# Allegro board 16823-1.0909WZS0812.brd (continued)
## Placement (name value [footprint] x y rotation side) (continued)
R6518  0R0402-PAD-2-GP  [0R0402-PAD-1]  143.21 18.16 180 bottom
R6519  0R0402-PAD-2-GP  [0R0402-PAD-1]  144.05 18.16 180 bottom
R6520  0R0402-PAD-2-GP  [0R0402-PAD-1]  132.34 26.52 180 bottom
R6521  0R2J-2-GP  [R402H16]  137.42 27.56 270 bottom
R6522  100R3J-4-GP  [R603H22]  133.26 22.58 270 bottom
R6523  0R2J-2-GP  [R402H16]  136.17 22.99 180 bottom
R6524  2K2R2J-2-GP  [R402H16]  133.69 17.74 270 bottom
R6525  10KR2J-3-GP  [R402H16]  139.12 27.82 270 bottom
R6601  0R2J-2-GP  [R402H16]  171.61 24.54 0 top
R6602  0R2J-2-GP  [R402H16]  171.89 21.54 0 top
R6603  0R3J-0-U-GP  [R603H22]  172.04 14.81 0 top
R7001  10KR2J-3-GP  [R402H16]  176.38 50.74 0 top
R7002  0R2J-2-GP  [R402H16]  174.13 43.88 180 top
R7003  0R2J-2-GP  [R402H16]  176.18 42.9 270 top
R7004  10KR2J-3-GP  [R402H16]  175.51 50.74 0 top
R7005  0R2J-2-GP  [R402H16]  174.62 50.74 0 top
R7006  100KR2J-1-GP  [R402H16]  166.78 83.52 270 top
R7007  100KR2J-1-GP  [R402H16]  160.08 83.56 0 top
R7008  100KR2J-1-GP  [R402H16]  177.04 48.3 0 top
R7009  100KR2J-1-GP  [R402H16]  160.64 81.64 90 top
R7010  0R2J-2-GP  [R402H16]  161.04 83.01 0 top
R7011  1MR2J-1-GP  [R402H16]  159.15 83.56 180 top
R9901  4K7R2F-GP  [R402H16]  39.71 69.14 180 top
R9902  0R2J-2-GP  [R402H16]  64.12 73.1 180 top
R9904  4K7R2F-GP  [R402H16]  47.07 62.18 180 top
R9905  10KR2J-3-GP  [R402H16]  55.43 74.63 0 top
R9906  1KR2J-1-GP  [R402H16]  53.7 74.63 180 top
R9908  0R2J-2-GP  [R402H16]  67.47 75.16 180 top
R9909  1KR2J-1-GP  [R402H16]  46.18 62.18 0 top
R9910  0R2J-2-GP  [R402H16]  64.47 68 90 top
R9912  1KR2J-1-GP  [R402H16]  39.71 67.41 0 top
R9913  0R2J-2-GP  [R402H16]  64.55 70.92 270 top
R9914  0R2J-2-GP  [R402H16]  157.18 83.34 0 bottom
R9915  0R2J-2-GP  [R402H16]  156.32 83.34 0 bottom
R9916  0R2J-2-GP  [R402H16]  65.56 75.03 180 top
R9917  1KR2J-1-GP  [R402H16]  56.27 74.63 180 top
R9918  0R2J-2-GP  [R402H16]  58.05 75.14 0 top
R9919  0R2J-2-GP  [R402H16]  49.54 73.56 90 top
R9920  0R2J-2-GP  [R402H16]  64.55 70.06 90 top
R9921  10KR2J-3-GP  [R402H16]  64.96 72.57 180 top
R9922  0R2J-2-GP  [R402H16]  59.77 75.14 0 top
R9923  0R2J-2-GP  [R402H16]  152.89 83.34 0 bottom
R9924  0R2J-2-GP  [R402H16]  49.54 74.4 90 top
R9925  0R2J-2-GP  [R402H16]  40.09 64.62 90 top
R9926  1KR2J-1-GP  [R402H16]  45.32 62.18 0 top
R9928  0R2J-2-GP  [R402H16]  153.75 83.34 0 bottom
R9929  0R2J-2-GP  [R402H16]  40.09 63.78 90 top
R9930  1KR2J-1-GP  [R402H16]  54.59 74.63 180 top
R9931  0R2J-2-GP  [R402H16]  154.62 83.34 0 bottom
R9932  0R2J-2-GP  [R402H16]  155.46 83.36 0 bottom
RN801  SRN2K2J-1-GP  [ARES2H16]  111.36 98.63 200 bottom
RN802  SRN2K2J-1-GP  [ARES2H16]  25.23 62.26 0 top
RN1201  SRN1KJ-7-GP  [SMD-ARES4H18]  89.77 30.23 90 top
RN1603  SRN10KJ-5-GP  [ARES2H18]  107.73 77.27 290 bottom
RN1606  SRN10KJ-5-GP  [ARES2H18]  107.04 79.17 290 bottom
RN1607  SRN10KJ-5-GP  [ARES2H18]  101.33 91.85 270 bottom
RN1608  SRN10KJ-5-GP  [ARES2H18]  103.11 89.82 270 bottom
RN1701  SRN10KJ-5-GP  [ARES2H18]  108.54 97.56 20 bottom
RN1703  SRN1KJ-7-GP  [SMD-ARES4H18]  90.71 82.6 180 bottom
RN1704  SRN2K2J-1-GP  [ARES2H16]  91.96 85.14 90 bottom
RN1802  SRN100J-3-GP  [SMD-ARES4H18]  128.3 104.83 20 bottom
RN1803  SRN10KJ-5-GP  [ARES2H18]  104.5 75.34 270 bottom
RN1804  SRN20KJ-1-GP  [SMD-ARES4H20]  103.51 97.61 40 bottom
RN1904  SRN10KJ-5-GP  [ARES2H18]  108.69 75.47 290 bottom
RN1905  0R8P4R-PAD-1-GP  [0R8P4R-PAD-1]  103.97 84.33 90 top
RN1906  SRN2K2J-1-GP  [ARES2H16]  142.73 20.04 270 bottom
RN1907  SRN10KJ-5-GP  [ARES2H18]  86.32 72.54 270 bottom
RN1908  SRN1KJ-7-GP  [SMD-ARES4H18]  69.4 65.84 0 top
RN1909  SRN1KJ-7-GP  [SMD-ARES4H18]  95.84 65.86 270 top
RN1910  SRN10KJ-5-GP  [ARES2H18]  101 140.72 90 bottom
RN1911  SRN10KJ-5-GP  [ARES2H18]  101 143.82 270 bottom
RN1912  SRN10KJ-5-GP  [ARES2H18]  104.12 146.92 270 bottom
RN2101  SRN10KJ-5-GP  [ARES2H18]  125.66 110.26 90 bottom
RN2401  SRN2K2J-1-GP  [ARES2H16]  171.28 52.63 180 top
RN2402  SRN10KJ-5-GP  [ARES2H18]  166.4 54.61 90 top
RN2404  SRN10KJ-5-GP  [ARES2H18]  170.52 65.18 90 top
RN2406  SRN10KJ-5-GP  [ARES2H18]  167.34 75.74 270 bottom
RN2601  SRN2K2J-1-GP  [ARES2H16]  74.18 67.01 90 bottom
RN2901  SRN2K2J-1-GP  [ARES2H16]  168.61 21.06 0 bottom
RN4302  SRN100J-4-GP  [ARES8-CN24H20]  150.2 178.16 270 top
RN5501  SRN100J-4-GP  [ARES8-CN24H20]  104.22 176.48 0 top
RN5502  SRN100J-3-GP  [SMD-ARES4H18]  113.8 168.28 180 top
RN5701  SRN2K2J-1-GP  [ARES2H16]  19.21 54.69 270 top
RN5702  SRN470J-3-GP  [ARES8-CN24H20]  15.93 46.59 90 bottom
RN5703  SRN470J-3-GP  [ARES8-CN24H20]  15.96 50.28 90 bottom
RN6401  SRN100J-3-GP  [SMD-ARES4H18]  167.55 114.81 90 bottom
RN6503  SRN33J-5-GP-U  [SMD-ARES4H18]  140.11 19.71 0 bottom
RN6504  SRN10KJ-5-GP  [ARES2H18]  138.06 21.47 180 bottom
RTC1  BAT-40-42010-00211RHF-GP-U2  [40-42010-00211RHF-U2]  35.35 23.5 180 bottom
SPI251  W25Q128FWSIQ-GP  [SOIC8-1H86]  60.37 48.99 270 bottom
SPI252  MX25U1001EMI-14G-GP  [SOIC8H69]  167.04 30.69 90 bottom
SPK1  ACES-CON4-29-GP  [50224-0040N-001]  155.2 8.3 180 bottom
SPR1  SPRING-63-GP  [SPR5630H142]  71.4 74.7 90 top
SPR2  SPRING-43-GP-U  [SPR4527H308]  158.56 34.3 270 bottom
SPR3  SPRING-63-GP  [SPR5630H142]  33.4 68.3 0 bottom
SPR4  SPRING-63-GP  [SPR5630H142]  71.4 47.3 90 top
SPR5  SPRING-63-GP  [SPR5630H142]  59.4 72.3 0 bottom
TP1  STAR-CON8-2-GP  [106H08-011001-A2-R]  138.9 10.1 90 bottom
TP509  TPAD14-OP-GP  [TPAD14-OP]  124.75 82.86 0 top
TP510  TPAD14-OP-GP  [TPAD14-OP]  126.58 81.41 0 top
TP1201  TPAD14-OP-GP  [TPAD14-OP]  143.8 28.63 270 top
TP1802  TPAD14-OP-GP  [TPAD14-OP]  117.76 91.37 0 top
TP1803  TPAD14-OP-GP  [TPAD14-OP]  126.98 103.23 180 bottom
TP1804  TPAD14-OP-GP  [TPAD14-OP]  113.49 98.27 180 bottom
TP1901  TPAD14-OP-GP  [TPAD14-OP]  112.78 87.89 0 top
TP2101  TPAD14-OP-GP  [TPAD14-OP]  122.56 101.6 180 bottom
TP2102  TPAD14-OP-GP  [TPAD14-OP]  121.17 101.12 180 bottom
TP2104  TPAD14-OP-GP  [TPAD14-OP]  118.6 92.51 0 top
TP2105  TPAD14-OP-GP  [TPAD14-OP]  115.6 99.04 180 bottom
TP2407  TPAD14-OP-GP  [TPAD14-OP]  165.82 69.88 180 bottom
TP2408  TPAD14-OP-GP  [TPAD14-OP]  156.04 55.25 180 bottom
TP2410  TPAD14-OP-GP  [TPAD14-OP]  175.19 69.9 180 bottom
TP2412  TPAD14-OP-GP  [TPAD14-OP]  156.67 65.08 180 bottom
TP2701  TPAD14-OP-GP  [TPAD14-OP]  156.9 24.82 180 bottom
TP4301  TPAD14-OP-GP  [TPAD14-OP]  148.42 175.11 0 top
TP4501  TPAD14-OP-GP  [TPAD14-OP]  52.71 44.1 0 top
TP6001  TPAD14-OP-GP  [TPAD14-OP]  171.97 149.61 0 top
TP6002  TPAD14-OP-GP  [TPAD14-OP]  171.76 148.59 180 bottom
TP6101  TPAD14-OP-GP  [TPAD14-OP]  143.09 157.05 0 top
TP6102  TPAD14-OP-GP  [TPAD14-OP]  144.58 155.68 0 top
TP6103  TPAD14-OP-GP  [TPAD14-OP]  156.4 163.43 180 bottom
TP6301  TPAD14-OP-GP  [TPAD14-OP]  59.42 62.92 0 top
TP6302  TPAD14-OP-GP  [TPAD14-OP]  58.17 62.94 0 top
TP6303  TPAD14-OP-GP  [TPAD14-OP]  56.93 62.97 0 top
TP6304  TPAD14-OP-GP  [TPAD14-OP]  53.42 62.97 0 top
TR5501  FILTER-4P-137-GP-U  [L125100-4P-4H28]  117.18 164.37 270 top
U1801  U74LVC1G08G-AL5-R-GP-U  [SC70-5-1H44]  95.63 92.21 270 bottom
U2404  G2129TL1U-GP  [SC70-6H44]  151.62 65.41 270 bottom
U2601  NCT7718W-GP  [MSOP8-1H44]  78.54 71.99 270 bottom
U3601  G524B2T11U-GP  [SOT-23-5H58]  22.33 37.09 270 top
U3602  G524B2T11U-GP  [SOT-23-5H58]  162.8 9.53 270 bottom
U4001  APL3523AQBI-TRG-GP  [SON14J3020-G2610H32]  27.74 51.23 90 top
U4002  APE8937GN2-GP-U  [DFN8G2-G1710-U1H32]  130.59 115.04 90 bottom
U4003  U74LVC1G08G-AL5-R-GP-U  [SC70-5-1H44]  22.28 60.86 180 bottom
U4004  U74LVC1G08G-AL5-R-GP-U  [SC70-5-1H44]  25.48 60.86 180 bottom
U5501  RT9724GB-GP  [SOT-23-5H51]  102.42 158.5 90 top
U6001  SN75LVCP601RTJR-GP  [QFN20-G2D25H32]  164.98 41.28 270 bottom
U6301  KLMBG4GEND-B031-GP  [BGA153G115130-1H40]  55.81 61.9 90 bottom
U7001  LNG2DMTR-GP  [LGA12G2H40]  174.81 47.68 0 top
USB1  SKT-USB13-179-GP  [SKT-USB13-157164-1]  4.87 31.55 90 bottom
USB2  SKT-USB13-179-GP  [SKT-USB13-157164-1]  4.87 13.05 90 bottom
WLAN1  SKT-NGFF75P-96-GP  [SM3ZS067U410TAR1000R-DT]  148.9 159 90 bottom
X1801  XTAL-32D768KHZ-68-GP  [SMD49-6914-0603H56]  92.31 78.54 225 bottom
X1901  XTAL-19D2MHZ-21-GP  [OSC-3225-4P-4H32]  130.82 108 200 bottom
XDP1  PAD-60P-1-NSP-GP  [PAD-60P-1-NSP]  52.18 68.33 180 top

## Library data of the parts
AFTP2501 AFTP2502 AFTP2901-AFTP2904 AFTP2908 AFTP2909 AFTP3501-AFTP3508 AFTP4301-AFTP4315 AFTP5501-AFTP5523 AFTP6101 AFTP6103 AFTP6104 AFTP6106-AFTP6108 AFTP6401-AFTP6404 AFTP6501-AFTP6503 AFTP6505-AFTP6508 AFTP6510-AFTP6513 AFTP6515-AFTP6540 AFTP6565-AFTP6567 AFTP6601-AFTP6612 = AFTE14P-75: tolerance: ZZ.AFT14.101
BATT1 = C144KA-108A7-L-1: tolerance: 20.81775.008
BATT2 = 50312-00841-001: tolerance: 020.80533.0008
C601 C1001-C1030 C1101-C1104 C1106-C1113 C1206-C1210 C1213-C1215 C1801 C1802 C2443 C2444 C2703 C2704 C3518 C3604 C3606 C4031 C5509 C5536 C6009 C6010 C6012 C6301 PC1101 PC4407 PC5028 PC5103 PC5109 PC5124 = C402H22: tolerance: 78.10523.5FL
C1201-C1203 C1205 C1211 C1212 C1216-C1218 C1220 C2602 C2707 C2709 C2712 C2713 C2723 C2729 C2901 C2903 C2904 C2906 C2908 C4002 C4004-C4006 C6102 C7001 C9901 PC1003 PC1004 PC1047 PC1052 PC5003 PC5004 PC5007 PC5008 PC5010 PC5024 PC5025 = C603H38: tolerance: 78.10610.5BL
C1223 C1224 C1805 C2417 C2418 C2428-C2432 C2436 C2438-C2442 C2445-C2447 C2502 C2504 C2601 C2605 C2606 C2706 C2708 C2710 C2714 C2717 C2719-C2721 C2728 C3509 C3517 C3605 C4010 C4011 C4030 C5502 C5538 C6020 C6022 C6101 C6103 C6303 C6305 C6401 C6501-C6504 C6601 C7002 C7003 C9902-C9905 EC4001-EC4005 EC6401 PC4501 PC4517 PC4518 = C402H22: tolerance: 78.10421.2FL
C1601 = C402H22: tolerance: 78.10421.2FL; signal model: Graser_C1601
C1602 = C402H22: tolerance: 78.10421.2FL; signal model: Graser_C1602
C1803 C1804 = C402H22: tolerance: 78.4R074.1FL
C1901 C1902 = C402H22: tolerance: 78.3R974.1FL
C2401 C2722 EC2708 EC5504 EC5505 = C402H22: tolerance: 78.22034.1FL
C2414 C2416 C2433 C2705 C5514 PC5023 PC5034 = C603H36: tolerance: 78.22523.5BL
C2501 C2503 = C402H22: tolerance: 078.10610.C5F1
C2603 C4003 = C402H22: tolerance: 78.47124.2FL
C2604 PC5011-PC5013 PC5026 PC5027 = C402H22: tolerance: 78.22224.2FL
C2607 EC2905-EC2908 PC4422 = C402H22: tolerance: 78.10134.1FL
C2701 C2702 C2711 C2715 C2716 C2718 C5510 C5515 C5516 C6302 C6304 PC4524 PC4526 = C603H36: tolerance: 78.47520.5BL
C2905 C2907 C2909 C2910 C4014 C4033 C5503 EC2702-EC2706 EC2901-EC2904 EC6403 PC5105 PC5122 PC5125 = C402H22: tolerance: 78.10224.2FL
C3501 = C402H22: tolerance: 78.10421.2FL; signal model: Graser_C3501
C3502 = C402H22: tolerance: 78.10421.2FL; signal model: Graser_C3502
C3507 = C402H22: tolerance: 78.10421.2FL; signal model: Graser_C3507
C3508 = C402H22: tolerance: 78.10421.2FL; signal model: Graser_C3508
C3515 C3601 C3602 PC5005 PC5006 PC5009 PC5017-PC5020 PC5022 PC5030-PC5032 = C805H58: tolerance: 78.22610.51L
C3607 = C1206H71: tolerance: 78.10710.52L
C5501 PC4408 PC4509 PC4529 = C805H54: tolerance: 78.47522.51L
C5504 = C402H22: tolerance: 78.10421.2FL; signal model: Graser_C5504
C5505 = C402H22: tolerance: 78.10421.2FL; signal model: Graser_C5505
C5506 = C402H22: tolerance: 78.10421.2FL; signal model: Graser_C5506
C5507 = C402H22: tolerance: 78.10421.2FL; signal model: Graser_C5507
C5511 EC4302 EC4307 EC4401 EC4402 EC5501-EC5503 EC5701 EC6402 EC6404 EC8901-EC8931 PC1023 PC1038 PC4402 PC4420 PC4421 PC4423 PC5015 PC5021 PC5029 PC5112 = C402H22: tolerance: 78.10422.5FL
C5512 = C402H22: tolerance: 78.10421.2FL; signal model: Graser_C5512
C5513 = C402H22: tolerance: 78.10421.2FL; signal model: Graser_C5513
C5701 = C402H22: tolerance: 78.10421.2FL; signal model: Graser_C5701
C5702 = C402H22: tolerance: 78.10421.2FL; signal model: Graser_C5702
C5703 = C402H22: tolerance: 78.10421.2FL; signal model: Graser_C5703
C5704 = C402H22: tolerance: 78.10421.2FL; signal model: Graser_C5704
C5705 = C402H22: tolerance: 78.10421.2FL; signal model: Graser_C5705
C5706 = C402H22: tolerance: 78.10421.2FL; signal model: Graser_C5706
C5707 = C402H22: tolerance: 78.10421.2FL; signal model: Graser_C5707
C5708 = C402H22: tolerance: 78.10421.2FL; signal model: Graser_C5708
C6001-C6008 PC4303-PC4305 PC4412 PC4425 PC4531 = C402H22: tolerance: 78.10324.2FL
C6011 = C402H22: tolerance: 78.10324.2FL; signal model: Graser_C6011
C6013 = C402H22: tolerance: 78.10324.2FL; signal model: Graser_C6013
C6014 = C402H22: tolerance: 78.10324.2FL; signal model: Graser_C6014
C6015 = C402H22: tolerance: 78.10324.2FL; signal model: Graser_C6015
C6016 = C402H22: tolerance: 78.10324.2FL; signal model: Graser_C6016
C6017 = C402H22: tolerance: 78.10324.2FL; signal model: Graser_C6017
C6018 = C402H22: tolerance: 78.10324.2FL; signal model: Graser_C6018
C6019 = C402H22: tolerance: 78.10324.2FL; signal model: Graser_C6019
C6021 C6023 C6024 = C805H54: tolerance: 78.10623.51L
CPU1 = BGA1296M3124H56: tolerance: ZZ.00CPU.061
D1601 = SOT23-2D4-312H44: tolerance: 83.00016.P11
D2401 = SOD323AKH38: tolerance: 83.R2004.G8F
D2701 D4001 D5501 D5502 = SOT23-2D4-312H48: tolerance: 75.00054.E7D
D4304-D4306 PD4302 = SOT23-2D4-312H44: tolerance: 75.00099.O7D
D5701 = SOT23-2D4-312H44: tolerance: 83.00056.Y11
DB1 = PAD-87212-1002N: tolerance: ZZ.00PAD.GV1
DB3 = 88459-047N: tolerance: 20.F1897.004
DCIN1 DCIN2 = 50458-00601-W01: tolerance: 20.F2132.006
DM1 = AS0A621-J4R6-7H-U: tolerance: 62.10024.S21
EC1801 EC1901 EC1902 EC2001 EC2002 EC2102 EC2503 EC2505 EC2709 EC4306 EC4309 EC4310 PC5033 = C402H22: tolerance: 78.10034.1FL
EC2401-EC2403 ED1201 ED1202 ED1803-ED1809 ED6401 = SOD882-10D6-1H20: tolerance: 83.05725.0A0
EC2501 EC2502 EC2504 EC2506 = C402H22: tolerance: 78.4R7B4.1FL
EC4301 PC4306 PC4416 PC4417 PC4426 PC4519 PC4527 PC4528 PC5102 PC5104 PC5113 PC5114 PC5119 PC5128 PC5131 = C805H56: tolerance: 78.10622.51L
EC4308 PC4302 PC4401 PC4403 PC4404 PC4409 PC4419 PC4516 PC4525 PC4530 PC4535 PC5106 PC5115 PC5116 PC5121 = C603H36: tolerance: 78.10424.2BL
EC5506 = C402H22: tolerance: 78.6R074.1FL
EC5507 EC6501-EC6506 = C402H22: tolerance: 78.33034.1FL
ED5701-ED5703 EU3501 EU3504 = SLP2510P8-1H22: tolerance: 075.00550.0071
ED6601 EU3502 EU5501 = SOT-6H58: tolerance: 075.09904.0A7C
EL3503 = L125100-4P-4H28: tolerance: 68.01012.20B; signal model: Graser_EL3503
EL3504 = L125100-4P-4H28: tolerance: 68.01012.20B; signal model: Graser_EL3504
EL4301-EL4304 R603 R701 R2708 R6004 R6025 = 0R0805-PAD-1-U: tolerance: ZZ.00PAD.M31
EL6601 = L125100-4P-4H28: tolerance: 68.01012.20B; signal model: Graser_EL6601
EL6602 = L125100-4P-4H28: tolerance: 68.01012.20B; signal model: Graser_EL6602
ER3505 = 0R0402-PAD-1: tolerance: ZZ.00PAD.M11; signal model: Graser_ER3505
ER3506 = 0R0402-PAD-1: tolerance: ZZ.00PAD.M11; signal model: Graser_ER3506
ER3509 = 0R0402-PAD-1: tolerance: ZZ.00PAD.M11; signal model: Graser_ER3509
ER3510 = 0R0402-PAD-1: tolerance: ZZ.00PAD.M11; signal model: Graser_ER3510
ER3511 = 0R0402-PAD-1: tolerance: ZZ.00PAD.M11; signal model: Graser_ER3511
ER3512 = 0R0402-PAD-1: tolerance: ZZ.00PAD.M11; signal model: Graser_ER3512
ER6102 = 0R0402-PAD-1: tolerance: ZZ.00PAD.M11; signal model: Graser_ER6102
ER6103 = 0R0402-PAD-1: tolerance: ZZ.00PAD.M11; signal model: Graser_ER6103
EU6001 = DFN10G2510H26: tolerance: 75.01045.073
F5501 F5503 = POLYSW-4633-UH43: tolerance: 69.50007.A31
F5502 = POLYSW-2114H50: tolerance: 69.50007.921
F5701 = POLYSW-2114H30: tolerance: 69.48001.081
FC3503-FC3506 = C402H22: tolerance: 78.1R074.1FL
G1801 G6401 G6402 = CON2O-U: tolerance: ZZ.CON2O.XXX
H1-H4 = HOLE335R115: tolerance: ZZ.00PAD.D01
H5 = HOLE276R91: tolerance: ZZ.00PAD.CZ1
H6-H9 = HOLE335R178: tolerance: ZZ.00PAD.7F1
H10 = HOLE384X421R115: tolerance: ZZ.SCREW.681
HDA27 = QFN48J6-G465H40: tolerance: 071.03246.0003
HDD1 = 132F12-010000-A2-R: tolerance: 020.K0125.0012
HDMI1 = SKT-HDMI23-188137-5: tolerance: 022.10025.0161
HS1 = STF236R128H101: tolerance: 34.4YG18.201
IOBD1 = 51519-03001-W02-U2: tolerance: 20.K0510.030
KB1 = 196370-30041-3: tolerance: 20.K0621.030
KB2 = 50699-03001-W01: tolerance: 020.K0254.0030
KBBL1 = 51678-00401-W01: tolerance: 020.K0206.0004
KBC24 = LQFP128H63: tolerance: 071.00985.000G
L2701 = L603H38: tolerance: 68.00115.091
LCD1 = 20455-040E-12: tolerance: 20.F1407.040
LED1 = LED3020-3P-19H44: tolerance: 083.1212A.0070
ODD1 ODD2 = 51519-02001-W03-U1: tolerance: 20.K0708.020
PC1001 PC1002 PC1006-PC1022 PC1024-PC1028 PC1030-PC1037 PC1039-PC1046 PC1048-PC1051 PC1102 PC1103 PC5035 PC5036 PC5101 PC5107 PC5108 PC5110 PC5117 PC5118 PC5120 PC5123 PC5126 PC5127 PC5129 PC5130 = C603H40: tolerance: 78.22610.5BL
PC4301 = C805H58: tolerance: 78.10594.41L
PC4406 PC4415 PC4418 = C805H56: tolerance: 78.10622.LAL
PC4410 = C603H36: tolerance: 78.47422.5BL
PC4411 = C402H22: tolerance: 78.47322.2FL
PC4413 = C603H36: tolerance: 78.33224.2BL
PC4433 = C402H22: tolerance: 78.47420.5FL
PC4434 = C603H36: tolerance: 78.10522.5BL
PC4435 = C402H22: tolerance: 78.22224.2FLDL
PC4520 = C603: tolerance: 78.33124.2BL
PC4522 PC4523 = C402H22: tolerance: 78.18034.1FL
PC4536 = C603: tolerance: 78.56124.2BL
PC5014 = C402H22: tolerance: 78.68124.2FL
PC5016 = C402H24: tolerance: 78.12224.2FL
PD4301 PD4401 = SOD323AKH38: tolerance: 83.2R004.08F
PD4303 = SOT-23-10H44: tolerance: 83.0024V.0A1
PD4304 = SOD123AK-2H43: tolerance: 83.SMF18.AAH
PD4404 = SOD323AKH42: tolerance: 83.04148.D1H
PG4402 PG4403 PG4407-PG4411 PG4517-PG4529 PG4531-PG4538 PG4540-PG4545 PG5003-PG5005 PG5007-PG5009 PG5011 PG5012 PG5014 PG5016 PG5101-PG5129 = GAP-CLOSE-PWR-3: tolerance: ZZ.CLOSE.001
PL4401 = L686647-127318H119: tolerance: 68.5R610.10U
PL4501 PL4502 = L7066-1830-UH119: tolerance: 68.2R210.20B
PL5001 = L2520-D620H48: tolerance: 068.2R210.1231
PL5002 = L32250525H48: tolerance: 068.1R010.1701
PL5003 = L2520-D620H48: tolerance: 068.1R010.1281
PL5101 = L7066-1630-1H119: tolerance: 68.R5610.10W
PL5102 = L7066-1830-UH119: tolerance: 68.R4710.10M
PL5103 = L7066-1830-UH119: tolerance: 68.R2210.10V
PQ4301 Q6401 = SOT23DGS2D4H48: tolerance: 84.05067.031
PQ4302 Q2601 Q2604 Q2902-Q2906 Q2908 Q5501 Q5504 = SOT23CBE2D4H44: tolerance: 84.T3904.H11
PQ4304 = SOT323CBE2D2H40: tolerance: 84.05212.B11
PQ4305 = SC70-2D2-312H44: tolerance: 84.00024.01K
PQ4306 Q7001 = SOT-363H44: tolerance: 84.2N702.A3F
PQ4402 PQ4407 PQ4408 PQ4410 Q1701 Q1902 Q1905 Q2403 Q2603 Q4001-Q4003 = SOT-363H44: tolerance: 75.27002.F7C
PQ4409 Q2401 = SOT23CBE2D4H44: tolerance: 84.T3906.E11
PQ4414 Q1601 Q1801 Q1802 Q2103 Q2104 Q2402 Q2502 Q2602 Q5702 Q5703 Q6505 Q6509 = SOT23DGS2D4H44: tolerance: 84.2N702.J31
PR4302 = R402H16: tolerance: 64.15025.6DL
PR4303 PR4401 PR4506 PR5029 PR5030 R1525 R1605 R1606 R1808 R1811 R1813 R1816 R1824 R1834 R1921 R2018-R2020 R2024 R2025 R2028 R2029 R2106 R2114 R2120 R2122 R2124 R2126 R2400 R2405 R2421 R2426 R2427 R2436 R2441 R2462 R2471-R2473 R2917 R2918 R5536 R5703 R6005 R6007 R6008 R6013 R6014 R6017 R6021 R6024 R6408 R6514 R6525 R7001 R7004 R9905 R9921 = R402H16: tolerance: 63.10334.1DL
PR4304 PR5016 PR5025 R2123 R2717 R5529-R5532 R6524 = R402H16: tolerance: 63.22234.1DL
PR4305 PR4306 R1905 R1908 = R402H16: tolerance: 63.33034.1DL
PR4307 = R603H22: tolerance: 63.24434.15L
PR4308 = R603H22: tolerance: 63.47333.15L
PR4309 PR4312 PR4403 PR4417 PR4419 PR4425 PR4430 PR4434 PR4438 PR4439 PR4469 PR4474 PR4534 PR5014 PR5018 R804 R805 R808 R1703 R1807 R1814 R1817 R1826 R2012 R2023 R2115 R2439 R2440 R2442 R2711 R2713 R2726 R2733 R3601 R4002 R4009 R4011 R5501-R5503 R5514 R5515 R5520 R5526-R5528 R5702 R6505 R6507 R6509 R7006-R7009 = R402H16: tolerance: 63.10434.1DL
PR4313 PR4422 PR4426 PR4502 PR4505 PR5001 PR5005 PR5010 PR5013 PR5017 PR5023 PR5033 PR5035 PR5037-PR5043 PR5113 R601 R611 R1201 R1213 R1607 R1702 R1804 R1809 R1829 R1830 R1909 R1919 R1924 R2013 R2128 R2129 R2414 R2415 R2422 R2425 R2444 R2497-R2501 R2503 R2505-R2509 R2512 R2529 R2530 R2603 R2611 R2705 R2710 R2718 R2719 R2722 R2724 R2729 R4004 R4301 R5504 R5505 R5517 R5518 R5701 R6001 R6002 R6404 R6405 R6508 R6518-R6520 = 0R0402-PAD-1: tolerance: ZZ.00PAD.M11
PR4314 = R1206H28: tolerance: 63.33232.11L
PR4317 PR4409 PR5105 PR5106 PR5109 R602 R604-R610 R702 R2435 R2720 R2725 R2727 R2728 R2901-R2904 R2906 R2907 R2909 R2911 R2914 R4050 R5512 R5718 R6105 = 0R0603-PAD-1-U: tolerance: ZZ.00PAD.M21
PR4402 PR4416 = R3720H40: tolerance: 64.R0105.7FL
PR4404 = R805H24: tolerance: 63.30231.16L
PR4405 = R402H16: tolerance: 63.47434.1DL
PR4406 PR4418 PR4465 PR4466 PR4468 PR4475 PR4476 PR4501 PR4503 PR4504 PR4525 PR4530 PR4535 PR5045 PR5046 R1801-R1803 R1805 R1818 R1911 R1912 R2014 R2016 R2017 R2117 R2118 R2404 R2411 R2412 R2494 R2511 R2515 R2518 R2601 R2602 R2607 R2609 R2706 R2707 R4005 R4008 R4010 R5510 R5535 R5537 R6003 R6106-R6108 R6310-R6312 R6314 R6315 R6317-R6321 R6323 R6325 R6511 R6515 R6521 R6523 R6601 R6602 R7002 R7003 R7005 R7010 R9902 R9908 R9910 R9913-R9916 R9918-R9920 R9922-R9925 R9928 R9929 R9931 R9932 = R402H16: tolerance: 63.R0034.1DL
PR4407 PR4429 = R402H16: tolerance: 64.30935.6DL
PR4408 = R805H24: tolerance: 63.20031.16L
PR4411 = R402H16: tolerance: 64.10235.6DL
PR4412 PR4415 = R402H16: tolerance: 64.33015.6DL
PR4413 = R402H16: tolerance: 64.16935.L0L
PR4414 = R402H16: tolerance: 63.33534.1DL
PR4420 = R402H16: tolerance: 64.7R505.6DL
PR4421 R2908 R2910 = R402H14: tolerance: 64.10R05.6DL
PR4423 = R402H16: tolerance: 64.59025.6DL
PR4424 = R402H16: tolerance: 64.84515.6DL
PR4427 = R402H16: tolerance: 64.78725.6DL
PR4431 = R402H16: tolerance: 64.47025.6DL
PR4432 PR4433 PR4436 = R402H16: tolerance: 64.12035.6DL
PR4435 PR4473 PR4523 PR5020 R1502 R1508 R1512 R1514 R1519 R1522 R1523 R2430 R2924-R2926 R2928 = R402H16: tolerance: 64.10025.6DL
PR4437 = R402H16: tolerance: 64.16035.6DL
PR4440 PR4529 PR4533 PR5102 PR5112 PR5114 = R805H24: tolerance: 64.2R205.16L
PR4464 = R402H16: tolerance: 63.68434.1DL
PR4470 R803 R7011 = R402H16: tolerance: 63.10534.1DL
PR4471 PR4472 PR4517 R2438 R2443 = R402H16: tolerance: 64.10035.6DL
PR4512 = R402H16: tolerance: 64.66515.6DL
PR4524 PR4528 = R603H22: tolerance: 63.1R534.15L
PR4526 = R402H16: tolerance: 64.97615.6DL
PR4527 = R402H16: tolerance: 64.15425.6DL
PR4531 = R402H16: tolerance: 64.13035.6DL
PR5004 PR5012 PR5034 = R402H14: tolerance: 64.10005.6DL
PR5007 PR5008 = R402H16: tolerance: 63.2R234.1DL
PR5019 = R402H16: tolerance: 64.54905.6DL
PR5021 = R402H16: tolerance: 64.38325.6DL
PR5024 = R402H16: tolerance: 64.21025.6DL
PR5031 PR5101 PR5103 PR5104 = R603H22: tolerance: 63.2R233.15L
PR5032 = R402H16: tolerance: 64.91015.6DL
PR5036 = R402H16: tolerance: 64.15825.6DL
PR5044 R1701 R1815 R1819 R1832 R1835 R1836 R1922 R1923 R2419 R2468 R2493 R2527 R2730 R2919 R2920 R2927 R2929 R4003 R4006 R4007 R4013 R6506 R6516 R9906 R9909 R9912 R9917 R9926 R9930 = R402H16: tolerance: 63.10234.1DL
PR5107 = NTC-402H24-U: tolerance: 069.60013.0001
PR5108 = R402H16: tolerance: 64.56205.6DL
PR5110 = R402H16: tolerance: 64.29415.6DL
PR5111 = R402H16: tolerance: 64.22605.6DL
PT4501 PT4502 = SE361414H178: tolerance: 79.22710.3KL
PT5101 = CT7343H83: tolerance: 79.22719.2BL
PT5102 = CT3528H79: tolerance: 77.C2271.45L
PT5103 = CT7343H83: tolerance: 79.33612.20L
PU4301 PU4402 PU4403 = PPAK-8P-3232H36: tolerance: 84.07403.037
PU4404 = QFN20G3D5-G2D15H40: tolerance: 74.24727.A73
PU4405 PU4406 PU4501 PU4504 PU4505 PU5101-PU5103 = PPAK-8P-3232H36: tolerance: 84.07410.A37
PU4502 PU5104 = PPAK-8P-3232H36: tolerance: 84.07506.037
PU4503 = QFN20-G1D75H32: tolerance: 74.51225.073
PU5001 = QFN52J6-G4D75H32: tolerance: 074.05073.0D73
PU5105 = PPAK-8P-G5324H44-COLAY: tolerance: ZZ.00215.037
PU5106-PU5108 = DFN8-G125065H32: tolerance: 74.09610.0E3
PWR1 = 50524-00401-001: tolerance: 020.K0005.0004
PWSW2 = TJE-533-S-V-T-R-744: tolerance: 62.40009.731
Q1901 Q1903 Q1904 = SOT-363H44: tolerance: 075.00138.0A7C
Q2101 Q2102 Q5503 Q6301 Q6508 = SOT23DGS2D4H44: tolerance: 084.00138.0A31
Q2404 Q6504 = SOT23DGS2D4H48: tolerance: 84.02130.031
Q2501 = SOT-23-9H44: tolerance: 75.00040.07D
Q2701 Q6501 = SOT23DGS2D4H44: tolerance: 084.03404.0A31
Q2907 = SOT23CBE2D4H44: tolerance: 84.T3906.A11
Q5701 = SOT-363H44: tolerance: 075.00138.0A7C; signal model: Graser_Q5701
Q6403 Q6404 Q6502 = SOT23CBE2D6H62: tolerance: 084.02418.0011
R801 R802 R1601 = R402H16: tolerance: 64.40205.6DL
R1207 R1208 R1211 R1212 = R402H16: tolerance: 64.36515.6DL
R1501 R1503-R1507 R1509-R1511 R1513 R1515-R1518 R1520 R1521 R1524 R1526 R9901 R9904 = R402H16: tolerance: 64.47015.6DL
R1806 R1812 R1827 R1828 = R402H16: tolerance: 63.51034.1DL
R1810 R2516 = R402H16: tolerance: 63.10634.1DL
R1823 R2119 R2125 R2492 = R402H16: tolerance: 63.20334.1DL
R1833 R5519 R5533 R5538 = R402H14: tolerance: 63.10134.1DL
R1907 R2715 = R402H16: tolerance: 64.20035.6DL
R2001 = R402H16: tolerance: 64.60R45.6DL
R2002 R2006 R2008 = R402H16: tolerance: 64.20005.6DL
R2003 = R402H16: tolerance: 64.13705.6DL
R2004 = R402H16: tolerance: 64.11305.6DL
R2005 R2007 R2009 R5704-R5707 = R402H16: tolerance: 64.15005.6DL
R2010 R2011 = R402H16: tolerance: 64.10505.6DL
R2101 = R402H16: tolerance: 64.10015.6DL
R2104 = R402H16: tolerance: 63.33034.1DL; signal model: Graser_R2104
R2105 = R402H16: tolerance: 63.33034.1DL; signal model: Graser_R2105
R2107 = R402H16: tolerance: 63.33034.1DL; signal model: Graser_R2107
R2116 R2522 R2523 R2532 R2535 R2912 R2913 R6012 R6016 R6020 R6022 R6513 = R402H16: tolerance: 63.47234.1DL
R2121 = R402H16: tolerance: 64.24905.6DL
R2401 = R402H16: tolerance: 63.33034.1DL; signal model: Graser_R2401
R2408 = R603H22: tolerance: 64.2R205.55L
R2416 = R402H16: tolerance: 63.33034.1DL; signal model: Graser_R2416
R2418 = R402H16: tolerance: 63.33034.1DL; signal model: Graser_R2418
R2437 = R402H16: tolerance: 63.47334.1DL
R2445 = R402H16: tolerance: 63.82234.1DL
R2489 R2491 = R402H16: tolerance: 63.33434.1DL
R2502 = R402H16: tolerance: 63.33034.1DL; signal model: Graser_R2502
R2510 = 0R0402-PAD-1: tolerance: ZZ.00PAD.M11; signal model: Graser_R2510
R2513 = 0R0402-PAD-1: tolerance: ZZ.00PAD.M11; signal model: Graser_R2513
R2514 = 0R0402-PAD-1: tolerance: ZZ.00PAD.M11; signal model: Graser_R2514
R2517 = 0R0402-PAD-1: tolerance: ZZ.00PAD.M11; signal model: Graser_R2517
R2528 = 0R0402-PAD-1: tolerance: ZZ.00PAD.M11; signal model: Graser_R2528
R2531 = 0R0402-PAD-1: tolerance: ZZ.00PAD.M11; signal model: Graser_R2531
R2533 R2534 = R402H16: tolerance: 63.33234.1DL
R2605 = R402H16: tolerance: 64.18725.6DL
R2606 = R402H16: tolerance: 64.20015.6DL
R2608 R2612 = R402H16: tolerance: 64.24925.6DL
R2610 = NTC-603H38: tolerance: 69.60035.041
R2613 = R402H16: tolerance: 63.20234.1DL
R2709 R2723 = R402H16: tolerance: 63.22034.1DL
R2712 R2716 R5507 = R805H24: tolerance: 63.R0031.16L
R2714 = R402H16: tolerance: 64.20025.6DL
R2721 = R402H16: tolerance: 63.22034.1DL; signal model: Graser_R2721
R2915 R2916 R2922 R2923 = R402H16: tolerance: 63.82234.L0L
R2921 R2930 = R402H16: tolerance: 63.22334.1DL
R3502 = 0R0402-PAD-1: tolerance: ZZ.00PAD.M11; signal model: Graser_R3502
R3503 = 0R0402-PAD-1: tolerance: ZZ.00PAD.M11; signal model: Graser_R3503
R4012 = R402H16: tolerance: 63.47134.1DL
R4049 R5522 R5523 R5525 R6322 R6327 R6504 R6517 R6603 = R603H22: tolerance: 63.00000.00L
R5506 = 0R0402-PAD-1: tolerance: ZZ.00PAD.M11; signal model: Graser_R5506
R5516 = 0R0402-PAD-1: tolerance: ZZ.00PAD.M11; signal model: Graser_R5516
R5534 = R402H16: tolerance: 63.20034.1DL
R6006 = 0R0402-PAD-1: tolerance: ZZ.00PAD.M11; signal model: Graser_R6006
R6009 = 0R0402-PAD-1: tolerance: ZZ.00PAD.M11; signal model: Graser_R6009
R6010 = 0R0402-PAD-1: tolerance: ZZ.00PAD.M11; signal model: Graser_R6010
R6011 = 0R0402-PAD-1: tolerance: ZZ.00PAD.M11; signal model: Graser_R6011
R6015 = 0R0402-PAD-1: tolerance: ZZ.00PAD.M11; signal model: Graser_R6015
R6018 = 0R0402-PAD-1: tolerance: ZZ.00PAD.M11; signal model: Graser_R6018
R6019 = 0R0402-PAD-1: tolerance: ZZ.00PAD.M11; signal model: Graser_R6019
R6023 = 0R0402-PAD-1: tolerance: ZZ.00PAD.M11; signal model: Graser_R6023
R6406 = R402H16: tolerance: 64.27405.6DL
R6407 = R402H16: tolerance: 64.42205.6DL
R6503 = R402H16: tolerance: 63.18434.1DL
R6522 = R603H22: tolerance: 63.10133.15L
RN801 RN802 RN1704 RN1906 RN2401 RN2601 RN2901 RN5701 = ARES2H16: tolerance: 66.22236.04L
RN1201 RN1703 RN1908 RN1909 = SMD-ARES4H18: tolerance: 66.10236.04L
RN1603 RN1606-RN1608 RN1701 RN1803 RN1904 RN1907 RN1910-RN1912 RN2101 RN2402 RN2404 RN2406 RN6504 = ARES2H18: tolerance: 66.10336.04L
RN1802 RN5502 RN6401 = SMD-ARES4H18: tolerance: 66.10136.04L
RN1804 = SMD-ARES4H20: tolerance: 66.20336.04L
RN1905 = 0R8P4R-PAD-1: tolerance: ZZ.0R08P.ZHH
RN4302 RN5501 = ARES8-CN24H20: tolerance: 66.10136.A8L
RN5702 RN5703 = ARES8-CN24H20: tolerance: 66.47136.08L
RN6503 = SMD-ARES4H18: tolerance: 66.33036.04L
RTC1 = 40-42010-00211RHF-U2: tolerance: 20.F2316.002
SPI251 = SOIC8-1H86: tolerance: 072.25128.0I01
SPI252 = SOIC8H69: tolerance: 072.25101.0001
SPK1 = 50224-0040N-001: tolerance: 20.F1639.004
SPR1 SPR3-SPR5 = SPR5630H142: tolerance: 34.4Y806.001
SPR2 = SPR4527H308: tolerance: 34.15J03.001
TP1 = 106H08-011001-A2-R: tolerance: 020.K0182.0008
TP509 TP510 TP1201 TP1802-TP1804 TP1901 TP2101 TP2102 TP2104 TP2105 TP2407 TP2408 TP2410 TP2412 TP2701 TP4301 TP4501 TP6001 TP6002 TP6101-TP6103 TP6301-TP6304 = TPAD14-OP: tolerance: ZZ.PAD14.001
TR5501 = L125100-4P-4H28: tolerance: 68.01012.20B
U1801 U4003 U4004 = SC70-5-1H44: tolerance: 73.01G08.EHG
U2404 = SC70-6H44: tolerance: 73.02129.02J
U2601 = MSOP8-1H44: tolerance: 74.07718.0B9
U3601 U3602 = SOT-23-5H58: tolerance: 074.00524.0C9F
U4001 = SON14J3020-G2610H32: tolerance: 74.03523.A73
U4002 = DFN8G2-G1710-U1H32: tolerance: 074.08937.0093
U5501 = SOT-23-5H51: tolerance: 74.09724.09F
U6001 = QFN20-G2D25H32: tolerance: 71.75601.003; signal model: Graser_U6001
U6301 = BGA153G115130-1H40: tolerance: 072.KMBG4.0C0U
U7001 = LGA12G2H40: tolerance: 074.LNG2D.00BZ
USB1 USB2 = SKT-USB13-157164-1: tolerance: 022.10005.0831
WLAN1 = SM3ZS067U410TAR1000R-DT: tolerance: 062.10003.0621
X1801 = SMD49-6914-0603H56: tolerance: 82.30001.G01
X1901 = OSC-3225-4P-4H32: tolerance: 082.30001.0061
XDP1 = PAD-60P-1-NSP: tolerance: ZZ.00PAD.GT1

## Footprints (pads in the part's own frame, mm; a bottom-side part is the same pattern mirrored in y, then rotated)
0R8P4R-PAD-1
  rect 0.61x0.838 smd: 1(-0.9,-0.486) 4(0.9,-0.486) 5(0.9,0.486) 8(-0.9,0.486)
  rect 0.305x0.838 smd: 2(-0.25,-0.486) 3(0.25,-0.486) 6(0.25,0.486) 7(-0.25,0.486)
0R0402-PAD-1
  custom 0.14x0.14 smd: 1(0,0.445) 2(0,-0.445)
0R0603-PAD-1-U
  custom 0.254x0.254 smd: 1(0,0.66) 2(0,-0.66)
0R0805-PAD-1-U
  rect 1.549x1.333 smd: 1(0,0.838) 2(0,-0.838)
40-42010-00211RHF-U2
  round 0.254 hole 0.914 unplated: (0,-8)
  round 0.254 hole 1.27 unplated: (0,8)
  custom 1.454x1.454 smd: 1(14.5,0)
  custom 1.899x1.899 smd: 2(-15.8,0)
106H08-011001-A2-R
  rect 0.305x1.295 smd: 1(-3.5,2.65) 2(-2.5,2.65) 3(-1.5,2.65) 4(-0.5,2.65) 5(0.5,2.65) 6(1.5,2.65) 7(2.5,2.65) 8(3.5,2.65)
  rect 1.803x1.397 smd: 9(-5.65,0) 10(5.65,0)
132F12-010000-A2-R
  rect 0.305x0.838 smd: 1(-2.75,3.175) 2(-2.25,3.175) 3(-1.75,3.175) 4(-1.25,3.175) 5(-0.75,3.175) 6(-0.25,3.175) 7(0.25,3.175) 8(0.75,3.175) 9(1.25,3.175) 10(1.75,3.175) 11(2.25,3.175) 12(2.75,3.175)
  rect 1.448x2.007 smd: 13(-5.125,0) 14(5.125,0)
20455-040E-12
  rect 0.305x0.889 smd: 1(-9.75,2.82) 2(-9.25,2.82) 3(-8.75,2.82) 4(-8.25,2.82) 5(-7.75,2.82) 6(-7.25,2.82) 7(-6.75,2.82) 8(-6.25,2.82) 9(-5.75,2.82) 10(-5.25,2.82) 11(-4.75,2.82) 12(-4.25,2.82) 13(-3.75,2.82) 14(-3.25,2.82) 15(-2.75,2.82) 16(-2.25,2.82) 17(-1.75,2.82) 18(-1.25,2.82) 19(-0.75,2.82) 20(-0.25,2.82) 21(0.25,2.82) 22(0.75,2.82) 23(1.25,2.82) 24(1.75,2.82) 25(2.25,2.82) 26(2.75,2.82) 27(3.25,2.82) 28(3.75,2.82) 29(4.25,2.82) 30(4.75,2.82) 31(5.25,2.82) 32(5.75,2.82) 33(6.25,2.82) 34(6.75,2.82) 35(7.25,2.82) 36(7.75,2.82) 37(8.25,2.82) 38(8.75,2.82) 39(9.25,2.82) 40(9.75,2.82)
  rect 0.559x0.889 smd: 41(-10.65,2.82) 42(10.65,2.82)
  rect 1.397x1.905 smd: 43(-12.849,0) 44(12.849,0)
50224-0040N-001
  rect 0.61x1.549 smd: 1(-1.5,3.875) 2(-0.5,3.875) 3(0.5,3.875) 4(1.5,3.875)
  rect 1.194x1.803 smd: 5(-2.797,0) 6(2.797,0)
50312-00841-001
  round 1.27 hole 0.889: 1(7,0) 2(5,0) 3(3,0) 4(1,0) 5(-1,0) 6(-3,0) 7(-5,0) 8(-7,0)
50458-00601-W01
  rect 0.559x1.295 smd: 1(5,5.025) 2(3,5.025) 3(1,5.025) 4(-1,5.025) 5(-3,5.025) 6(-5,5.025)
  rect 1.295x2.057 smd: 7(8.1,0) 8(-8.1,0)
50524-00401-001
  rect 0.305x1.295 smd: 1(-1.5,5.65) 2(-0.5,5.65) 3(0.5,5.65) 4(1.5,5.65)
  rect 1.803x2.21 smd: 5(-4.15,0) 6(4.15,0)
50699-03001-W01
  rect 0.229x0.813 smd: 1(-11.6,3.3) 2(-10.8,3.3) 3(-10,3.3) 4(-9.2,3.3) 5(-8.4,3.3) 6(-7.6,3.3) 7(-6.8,3.3) 8(-6,3.3) 9(-5.2,3.3) 10(-4.4,3.3) 11(-3.6,3.3) 12(-2.8,3.3) 13(-2,3.3) 14(-1.2,3.3) 15(-0.4,3.3) 16(0.4,3.3) 17(1.2,3.3) 18(2,3.3) 19(2.8,3.3) 20(3.6,3.3) 21(4.4,3.3) 22(5.2,3.3) 23(6,3.3) 24(6.8,3.3) 25(7.6,3.3) 26(8.4,3.3) 27(9.2,3.3) 28(10,3.3) 29(10.8,3.3) 30(11.6,3.3)
  rect 0.559x1.295 smd: 31(-13.075,0) 32(13.075,0)
51519-02001-W03-U1
  rect 0.305x1.295 smd: 1(-4.75,5.65) 2(-4.25,5.65) 3(-3.75,5.65) 4(-3.25,5.65) 5(-2.75,5.65) 6(-2.25,5.65) 7(-1.75,5.65) 8(-1.25,5.65) 9(-0.75,5.65) 10(-0.25,5.65) 11(0.25,5.65) 12(0.75,5.65) 13(1.25,5.65) 14(1.75,5.65) 15(2.25,5.65) 16(2.75,5.65) 17(3.25,5.65) 18(3.75,5.65) 19(4.25,5.65) 20(4.75,5.65)
  rect 1.803x2.21 smd: 21(-6.9,0) 22(6.9,0)
51519-03001-W02-U2
  rect 0.305x1.295 smd: 1(-7.25,5.65) 2(-6.75,5.65) 3(-6.25,5.65) 4(-5.75,5.65) 5(-5.25,5.65) 6(-4.75,5.65) 7(-4.25,5.65) 8(-3.75,5.65) 9(-3.25,5.65) 10(-2.75,5.65) 11(-2.25,5.65) 12(-1.75,5.65) 13(-1.25,5.65) 14(-0.75,5.65) 15(-0.25,5.65) 16(0.25,5.65) 17(0.75,5.65) 18(1.25,5.65) 19(1.75,5.65) 20(2.25,5.65) 21(2.75,5.65) 22(3.25,5.65) 23(3.75,5.65) 24(4.25,5.65) 25(4.75,5.65) 26(5.25,5.65) 27(5.75,5.65) 28(6.25,5.65) 29(6.75,5.65) 30(7.25,5.65)
  rect 1.803x2.21 smd: 31(-9.4,0) 32(9.4,0)
51678-00401-W01
  rect 0.406x0.838 smd: 1(-1.5,3.175) 2(-0.5,3.175) 3(0.5,3.175) 4(1.5,3.175)
  rect 0.813x2.007 smd: 5(-3.7,0) 6(3.7,0)
88459-047N
  rect 0.508x0.991 smd: 1(1.2,1.455) 2(0.4,1.455) 3(-0.4,1.455) 4(-1.2,1.455)
  rect 1.194x1.702 smd: 5(2.5,0) 6(-2.5,0)
196370-30041-3
  rect 0.406x1.295 smd: 1(-11.6,5.65) 2(-10.8,5.65) 3(-10,5.65) 4(-9.2,5.65) 5(-8.4,5.65) 6(-7.6,5.65) 7(-6.8,5.65) 8(-6,5.65) 9(-5.2,5.65) 10(-4.4,5.65) 11(-3.6,5.65) 12(-2.8,5.65) 13(-2,5.65) 14(-1.2,5.65) 15(-0.4,5.65) 16(0.4,5.65) 17(1.2,5.65) 18(2,5.65) 19(2.8,5.65) 20(3.6,5.65) 21(4.4,5.65) 22(5.2,5.65) 23(6,5.65) 24(6.8,5.65) 25(7.6,5.65) 26(8.4,5.65) 27(9.2,5.65) 28(10,5.65) 29(10.8,5.65) 30(11.6,5.65)
  rect 1.854x2.21 smd: 31(-13.975,0) 32(13.975,0)
AFTE14P-75
  round 0.356 smd: 1(0,0)
ARES2H16
  rect 0.356x0.66 smd: 1(-0.325,-0.599) 2(0.325,-0.599) 3(0.325,0.599) 4(-0.325,0.599)
ARES2H18
  rect 0.356x0.66 smd: 1(-0.325,-0.599) 2(0.325,-0.599) 3(0.325,0.599) 4(-0.325,0.599)
ARES8-CN24H20
  rect 0.61x0.66 smd: 1(-0.9,-0.486) 4(0.9,-0.486) 5(0.9,0.486) 8(-0.9,0.486)
  rect 0.305x0.66 smd: 2(-0.25,-0.486) 3(0.25,-0.486) 6(0.25,0.486) 7(-0.25,0.486)
AS0A621-J4R6-7H-U
  round 0.254 hole 1.118 unplated: (-33.4,0)
  round 0.254 hole 1.6 unplated: (33.4,0)
  custom 0.114x0.114 smd: 1(31.65,4.1) 2(31.35,-4.1) 3(31.05,4.1) 4(30.751,-4.1) 5(30.45,4.1) 6(30.15,-4.1) 7(29.85,4.1) 8(29.55,-4.1) 9(29.251,4.1) 10(28.95,-4.1) 11(28.65,4.1) 12(28.35,-4.1) 13(28.051,4.1) 14(27.751,-4.1) 15(27.45,4.1) 16(27.15,-4.1) 17(26.851,4.1) 18(26.551,-4.1) 19(26.25,4.1) 20(25.95,-4.1) 21(25.65,4.1) 22(25.35,-4.1) 23(25.051,4.1) 24(24.75,-4.1) 25(24.45,4.1) 26(24.15,-4.1) 27(23.851,4.1) 28(23.55,-4.1) 29(23.25,4.1) 30(22.95,-4.1) 31(22.651,4.1) 32(22.351,-4.1) 33(22.05,4.1) 34(21.75,-4.1) 35(21.451,4.1) 36(21.151,-4.1) 37(20.85,4.1) 38(20.55,-4.1) 39(20.25,4.1) 40(19.95,-4.1) 41(19.65,4.1) 42(19.35,-4.1) 43(19.049,4.1) 44(18.749,-4.1) 45(18.45,4.1) 46(18.15,-4.1) 47(17.85,4.1) 48(17.549,-4.1) 49(17.25,4.1) 50(16.95,-4.1) 51(16.65,4.1) 52(16.349,-4.1) 53(16.049,4.1) 54(15.75,-4.1) 55(15.45,4.1) 56(15.15,-4.1) 57(14.849,4.1) 58(14.549,-4.1) 59(14.25,4.1) 60(13.95,-4.1) 61(13.649,4.1) 62(13.349,-4.1) 63(13.05,4.1) 64(12.75,-4.1) 65(12.45,4.1) 66(12.149,-4.1) 67(11.85,4.1) 68(11.55,-4.1) 69(11.25,4.1) 70(10.95,-4.1) 71(10.649,4.1) 72(10.349,-4.1) 73(7.65,4.1) 74(7.35,-4.1) 75(7.049,4.1) 76(6.749,-4.1) 77(6.45,4.1) 78(6.15,-4.1) 79(5.85,4.1) 80(5.549,-4.1) 81(5.25,4.1) 82(4.95,-4.1) 83(4.65,4.1) 84(4.349,-4.1) 85(4.05,4.1) 86(3.75,-4.1) 87(3.45,4.1) 88(3.15,-4.1) 89(2.849,4.1) 90(2.549,-4.1) 91(2.25,4.1) 92(1.95,-4.1) 93(1.649,4.1) 94(1.349,-4.1) 95(1.05,4.1) 96(0.75,-4.1) 97(0.45,4.1) 98(0.149,-4.1) 99(-0.15,4.1) 100(-0.45,-4.1) 101(-0.75,4.1) 102(-1.051,-4.1) 103(-1.351,4.1) 104(-1.65,-4.1) 105(-1.95,4.1) 106(-2.25,-4.1) 107(-2.551,4.1) 108(-2.851,-4.1) 109(-3.15,4.1) 110(-3.45,-4.1) 111(-3.751,4.1) 112(-4.051,-4.1) 113(-4.35,4.1) 114(-4.65,-4.1) 115(-4.95,4.1) 116(-5.251,-4.1) 117(-5.55,4.1) 118(-5.85,-4.1) 119(-6.15,4.1) 120(-6.451,-4.1) 121(-6.751,4.1) 122(-7.051,-4.1) 123(-7.35,4.1) 124(-7.65,-4.1) 125(-7.951,4.1) 126(-8.251,-4.1) 127(-8.55,4.1) 128(-8.85,-4.1) 129(-9.15,4.1) 130(-9.451,-4.1) 131(-9.75,4.1) 132(-10.05,-4.1) 133(-10.35,4.1) 134(-10.651,-4.1) 135(-10.95,4.1) 136(-11.25,-4.1) 137(-11.55,4.1) 138(-11.85,-4.1) 139(-12.151,4.1) 140(-12.451,-4.1) 141(-12.75,4.1) 142(-13.05,-4.1) 143(-13.351,4.1) 144(-13.651,-4.1) 145(-13.95,4.1) 146(-14.25,-4.1) 147(-14.55,4.1) 148(-14.851,-4.1) 149(-15.15,4.1) 150(-15.45,-4.1) 151(-15.75,4.1) 152(-16.051,-4.1) 153(-16.35,4.1) 154(-16.65,-4.1) 155(-16.95,4.1) 156(-17.25,-4.1) 157(-17.551,4.1) 158(-17.851,-4.1) 159(-18.15,4.1) 160(-18.45,-4.1) 161(-18.751,4.1) 162(-19.051,-4.1) 163(-19.35,4.1) 164(-19.65,-4.1) 165(-19.95,4.1) 166(-20.251,-4.1) 167(-20.55,4.1) 168(-20.85,-4.1) 169(-21.15,4.1) 170(-21.451,-4.1) 171(-21.751,4.1) 172(-22.051,-4.1) 173(-22.35,4.1) 174(-22.65,-4.1) 175(-22.951,4.1) 176(-23.251,-4.1) 177(-23.55,4.1) 178(-23.85,-4.1) 179(-24.151,4.1) 180(-24.451,-4.1) 181(-24.75,4.1) 182(-25.05,-4.1) 183(-25.35,4.1) 184(-25.651,-4.1) 185(-25.95,4.1) 186(-26.25,-4.1) 187(-26.55,4.1) 188(-26.851,-4.1) 189(-27.151,4.1) 190(-27.451,-4.1) 191(-27.75,4.1) 192(-28.05,-4.1) 193(-28.351,4.1) 194(-28.651,-4.1) 195(-28.95,4.1) 196(-29.25,-4.1) 197(-29.55,4.1) 198(-29.851,-4.1) 199(-30.15,4.1) 200(-30.45,-4.1) 201(-30.75,4.1) 202(-31.05,-4.1) 203(-31.349,4.1) 204(-31.649,-4.1)
  rect 4.496x4.597 smd: 205(32.8,12) 206(-32.8,12)
BGA153G115130-1H40
  oval 0.229x0.356 smd: A1(-3.25,3.25) A2(-2.75,3.25) A3(-2.25,3.25) A4(-1.75,3.25) A5(-1.25,3.25) A6(-0.75,3.25)
  round 0.356 smd: A7(-0.25,3.25) A8(0.25,3.25) A9(0.75,3.25) A10(1.25,3.25) A11(1.75,3.25) A12(2.25,3.25) A13(2.75,3.25) A14(3.25,3.25) B2(-2.75,2.75) B3(-2.25,2.75) B4(-1.75,2.75) B5(-1.25,2.75) B6(-0.75,2.75) B7(-0.25,2.75) B8(0.25,2.75) B9(0.75,2.75) B10(1.25,2.75) B11(1.75,2.75) B12(2.25,2.75) B13(2.75,2.75) B14(3.25,2.75) C2(-2.75,2.25) C3(-2.25,2.25) C4(-1.75,2.25) C5(-1.25,2.25) C6(-0.75,2.25) C7(-0.25,2.25) C8(0.25,2.25) C9(0.75,2.25) C10(1.25,2.25) C11(1.75,2.25) C12(2.25,2.25) C13(2.75,2.25) C14(3.25,2.25) D1(-3.25,1.75) D2(-2.75,1.75) D3(-2.25,1.75) D4(-1.75,1.75) D12(2.25,1.75) D13(2.75,1.75) D14(3.25,1.75) E1(-3.25,1.25) E2(-2.75,1.25) E3(-2.25,1.25) E5(-1.25,1.25) E6(-0.75,1.25) E7(-0.25,1.25) E8(0.25,1.25) E9(0.75,1.25) E10(1.25,1.25) E12(2.25,1.25) E13(2.75,1.25) E14(3.25,1.25) F1(-3.25,0.75) F2(-2.75,0.75) F3(-2.25,0.75) F5(-1.25,0.75) F10(1.25,0.75) F12(2.25,0.75) F13(2.75,0.75) F14(3.25,0.75) G1(-3.25,0.25) G2(-2.75,0.25) G3(-2.25,0.25) G5(-1.25,0.25) G10(1.25,0.25) G12(2.25,0.25) G13(2.75,0.25) G14(3.25,0.25) H1(-3.25,-0.25) H2(-2.75,-0.25) H3(-2.25,-0.25) H5(-1.25,-0.25) H10(1.25,-0.25) H12(2.25,-0.25) H13(2.75,-0.25) H14(3.25,-0.25) J1(-3.25,-0.75) J2(-2.75,-0.75) J3(-2.25,-0.75) J5(-1.25,-0.75) J10(1.25,-0.75) J12(2.25,-0.75) J13(2.75,-0.75) J14(3.25,-0.75) K1(-3.25,-1.25) K2(-2.75,-1.25) K3(-2.25,-1.25) K5(-1.25,-1.25) K6(-0.75,-1.25) K7(-0.25,-1.25) K8(0.25,-1.25) K9(0.75,-1.25) K10(1.25,-1.25) K12(2.25,-1.25) K13(2.75,-1.25) K14(3.25,-1.25) L1(-3.25,-1.75) L2(-2.75,-1.75) L3(-2.25,-1.75) L12(2.25,-1.75) L13(2.75,-1.75) L14(3.25,-1.75) M2(-2.75,-2.25) M3(-2.25,-2.25) M4(-1.75,-2.25) M5(-1.25,-2.25) M6(-0.75,-2.25) M7(-0.25,-2.25) M8(0.25,-2.25) M9(0.75,-2.25) M10(1.25,-2.25) M11(1.75,-2.25) M12(2.25,-2.25) M13(2.75,-2.25) M14(3.25,-2.25) N2(-2.75,-2.75) N3(-2.25,-2.75) N4(-1.75,-2.75) N5(-1.25,-2.75) N6(-0.75,-2.75) N7(-0.25,-2.75) N8(0.25,-2.75) N9(0.75,-2.75) N10(1.25,-2.75) N11(1.75,-2.75) N12(2.25,-2.75) N13(2.75,-2.75) N14(3.25,-2.75) P2(-2.75,-3.25) P3(-2.25,-3.25) P4(-1.75,-3.25) P5(-1.25,-3.25) P6(-0.75,-3.25) P7(-0.25,-3.25) P8(0.25,-3.25) P9(0.75,-3.25) P10(1.25,-3.25) P11(1.75,-3.25) P12(2.25,-3.25) P13(2.75,-3.25) P14(3.25,-3.25)
  oval 0.356x0.229 smd: B1(-3.25,2.75) C1(-3.25,2.25) M1(-3.25,-2.25) N1(-3.25,-2.75) P1(-3.25,-3.25)
BGA1296M3124H56
  round 0.47 smd: A3(13.954,-11.314) A62(-14.382,-11.314) B2(14.383,-10.883) B63(-14.814,-10.883) BH1(14.814,10.883) BH63(-14.814,10.883) BJ2(14.382,11.314) BJ62(-14.382,11.314) C1(14.814,-10.454)
  round 0.356 smd: A4(13.221,-11.314) A5(12.548,-11.314) A7(11.697,-11.314) A9(11.024,-11.314) A56(-11.411,-11.314) A58(-12.439,-11.314) A60(-13.112,-11.314) A61(-13.786,-11.314) B3(13.759,-10.72) B4(13.162,-10.72) B5(12.565,-10.72) B8(11.371,-10.72) B57(-11.841,-10.72) B58(-12.438,-10.72) B60(-13.035,-10.72) B61(-13.632,-10.72) B62(-14.238,-10.738) BB1(14.814,8.089) BB63(-14.814,8.089) BC2(14.22,8.354) BC62(-14.22,8.354) BD1(14.814,8.94) BD2(14.22,8.95) BD62(-14.22,8.95) BD63(-14.814,8.94) BE1(14.814,9.613) BE2(14.22,9.547) BE62(-14.22,9.547) BE63(-14.814,9.613) BG1(14.814,10.286) BG2(14.22,10.144) BG62(-14.22,10.144) BG63(-14.814,10.286) BH2(14.238,10.738) BH3(13.632,10.72) BH4(13.035,10.72) BH6(12.438,10.72) BH7(11.841,10.72) BH57(-11.841,10.72) BH58(-12.438,10.72) BH60(-13.035,10.72) BH61(-13.632,10.72) BH62(-14.238,10.738) BJ3(13.786,11.314) BJ4(13.112,11.314) BJ6(12.439,11.314) BJ8(11.411,11.314) BJ56(-11.411,11.314) BJ58(-12.439,11.314) BJ60(-13.112,11.314) BJ61(-13.786,11.314) C2(14.22,-10.259) C62(-14.22,-10.144) C63(-14.814,-10.286) D1(14.814,-9.724) D2(14.22,-9.665) E62(-14.22,-9.547) E63(-14.814,-9.613) F1(14.814,-9.051) F2(14.22,-9.072) F62(-14.22,-8.95) F63(-14.814,-8.94) G1(14.814,-8.2) G2(14.258,-8.474) G62(-14.22,-8.354) H63(-14.814,-8.089) J1(14.814,-7.527)
  oval 0.254x0.343 smd: A10(10.198,-11.314) A12(9.271,-11.314) A14(8.344,-11.314) A16(7.417,-11.314) A18(6.49,-11.314) A20(5.563,-11.314) A22(4.636,-11.314) A24(3.708,-11.314) A26(2.781,-11.314) A28(1.854,-11.314) A30(0.927,-11.314) A32(0,-11.314) A34(-0.927,-11.314) A36(-1.854,-11.314) A38(-2.781,-11.314) A40(-3.708,-11.314) A42(-4.636,-11.314) A44(-5.563,-11.314) A46(-6.49,-11.314) A48(-7.417,-11.314) A50(-8.344,-11.314) A52(-9.271,-11.314) A54(-10.198,-11.314) BJ10(10.198,11.314) BJ12(9.271,11.314) BJ14(8.344,11.314) BJ16(7.417,11.314) BJ18(6.49,11.314) BJ20(5.563,11.314) BJ22(4.636,11.314) BJ24(3.708,11.314) BJ26(2.781,11.314) BJ28(1.854,11.314) BJ30(0.927,11.314) BJ32(0,11.314) BJ34(-0.927,11.314) BJ36(-1.854,11.314) BJ38(-2.781,11.314) BJ40(-3.708,11.314) BJ42(-4.636,11.314) BJ44(-5.563,11.314) BJ46(-6.49,11.314) BJ48(-7.417,11.314) BJ50(-8.344,11.314) BJ52(-9.271,11.314) BJ54(-10.198,11.314)
  oval 0.343x0.254 smd: AA1(14.814,-1.854) AA63(-14.814,-1.854) AC1(14.814,-0.927) AC63(-14.814,-0.927) AE1(14.814,0) AE63(-14.814,0) AG1(14.814,0.927) AG63(-14.814,0.927) AJ1(14.814,1.854) AJ63(-14.814,1.854) AL1(14.814,2.781) AL63(-14.814,2.781) AN1(14.814,3.708) AN63(-14.814,3.708) AR1(14.814,4.636) AR63(-14.814,4.636) AU1(14.814,5.563) AU63(-14.814,5.563) AW1(14.814,6.49) AW63(-14.814,6.49) BA1(14.814,7.417) BA63(-14.814,7.417) J63(-14.814,-7.417) L1(14.814,-6.49) L63(-14.814,-6.49) N1(14.814,-5.563) N63(-14.814,-5.563) R1(14.814,-4.636) R63(-14.814,-4.636) U1(14.814,-3.708) U63(-14.814,-3.708) W1(14.814,-2.781) W63(-14.814,-2.781)
  round 0.279 smd: AA2(14.037,-1.854) AA62(-14.037,-1.854) AB2(14.414,-1.391) AB3(13.66,-1.391) AB61(-13.66,-1.391) AB62(-14.414,-1.391) AC2(14.037,-0.927) AC62(-14.037,-0.927) AD2(14.414,-0.464) AD3(13.66,-0.464) AD61(-13.66,-0.464) AD62(-14.414,-0.464) AE2(14.037,0) AE4(13.285,0) AE60(-13.285,0) AE62(-14.037,0) AF2(14.414,0.464) AF3(13.66,0.464) AF61(-13.66,0.464) AF62(-14.414,0.464) AG2(14.037,0.927) AG62(-14.037,0.927) AH2(14.414,1.391) AH3(13.66,1.391) AH61(-13.66,1.391) AH62(-14.414,1.391) AJ2(14.037,1.854) AJ62(-14.037,1.854) AK2(14.414,2.318) AK3(13.66,2.318) AK61(-13.66,2.318) AK62(-14.414,2.318) AL2(14.037,2.781) AL62(-14.037,2.781) AM2(14.414,3.245) AM3(13.66,3.245) AM61(-13.66,3.245) AM62(-14.414,3.245) AN2(14.037,3.708) AN62(-14.037,3.708) AP2(14.414,4.172) AP3(13.66,4.172) AP61(-13.66,4.172) AP62(-14.414,4.172) AR2(14.037,4.636) AR62(-14.037,4.636) AT2(14.414,5.099) AT3(13.66,5.099) AT61(-13.66,5.099) AT62(-14.414,5.099) AU2(14.037,5.563) AU62(-14.037,5.563) AV2(14.414,6.026) AV3(13.66,6.026) AV61(-13.66,6.026) AV62(-14.414,6.026) AW2(14.037,6.49) AW62(-14.037,6.49) AY2(14.414,6.953) AY3(13.66,6.953) AY61(-13.66,6.953) AY62(-14.414,6.953) B9(10.774,-10.745) B11(9.735,-10.914) B13(8.807,-10.914) B15(7.88,-10.914) B17(6.953,-10.914) B19(6.026,-10.914) B21(5.099,-10.914) B23(4.172,-10.914) B25(3.245,-10.914) B27(2.318,-10.914) B29(1.391,-10.914) B31(0.464,-10.914) B33(-0.464,-10.914) B35(-1.391,-10.914) B37(-2.318,-10.914) B39(-3.245,-10.914) B41(-4.172,-10.914) B43(-5.099,-10.914) B45(-6.026,-10.914) B47(-6.953,-10.914) B49(-7.88,-10.914) B51(-8.807,-10.914) B53(-9.735,-10.914) B55(-10.662,-10.914) BA2(14.22,7.544) BA62(-14.22,7.544) BF32(0,9.78) BG7(11.589,10.159) BG8(11.125,10.537) BG9(10.662,10.159) BG10(10.198,10.537) BG11(9.735,10.159) BG12(9.271,10.537) BG13(8.807,10.159) BG14(8.344,10.537) BG15(7.88,10.159) BG16(7.417,10.537) BG17(6.953,10.159) BG18(6.49,10.537) BG19(6.026,10.159) BG20(5.563,10.537) BG21(5.099,10.159) BG22(4.636,10.537) BG23(4.172,10.159) BG24(3.708,10.537) BG25(3.245,10.159) BG26(2.781,10.537) BG27(2.318,10.159) BG28(1.854,10.537) BG29(1.391,10.159) BG30(0.927,10.537) BG31(0.464,10.159) BG32(0,10.537) BG33(-0.464,10.159) BG34(-0.927,10.537) BG35(-1.391,10.159) BG36(-1.854,10.537) BG37(-2.318,10.159) BG38(-2.781,10.537) BG39(-3.245,10.159) BG40(-3.708,10.537) BG41(-4.172,10.159) BG42(-4.636,10.537) BG43(-5.099,10.159) BG44(-5.563,10.537) BG45(-6.026,10.159) BG46(-6.49,10.537) BG47(-6.953,10.159) BG48(-7.417,10.537) BG49(-7.88,10.159) BG50(-8.344,10.537) BG51(-8.807,10.159) BG52(-9.271,10.537) BG53(-9.735,10.159) BG54(-10.198,10.537) BG55(-10.662,10.159) BG56(-11.125,10.537) BG57(-11.589,10.159) BH9(10.662,10.914) BH11(9.735,10.914) BH13(8.807,10.914) BH15(7.88,10.914) BH17(6.953,10.914) BH19(6.026,10.914) BH21(5.099,10.914) BH23(4.172,10.914) BH25(3.245,10.914) BH27(2.318,10.914) BH29(1.391,10.914) BH31(0.464,10.914) BH33(-0.464,10.914) BH35(-1.391,10.914) BH37(-2.318,10.914) BH39(-3.245,10.914) BH41(-4.172,10.914) BH43(-5.099,10.914) BH45(-6.026,10.914) BH47(-6.953,10.914) BH49(-7.88,10.914) BH51(-8.807,10.914) BH53(-9.735,10.914) BH55(-10.662,10.914) C9(10.662,-10.159) C10(10.198,-10.537) C11(9.735,-10.159) C12(9.271,-10.537) C13(8.807,-10.159) C14(8.344,-10.537) C15(7.88,-10.159) C16(7.417,-10.537) C17(6.953,-10.159) C18(6.49,-10.537) C19(6.026,-10.159) C20(5.563,-10.537) C21(5.099,-10.159) C22(4.636,-10.537) C23(4.172,-10.159) C24(3.708,-10.537) C25(3.245,-10.159) C26(2.781,-10.537) C27(2.318,-10.159) C28(1.854,-10.537) C29(1.391,-10.159) C30(0.927,-10.537) C31(0.464,-10.159) C32(0,-10.537) C33(-0.464,-10.159) C34(-0.927,-10.537) C35(-1.391,-10.159) C36(-1.854,-10.537) C37(-2.318,-10.159) C38(-2.781,-10.537) C39(-3.245,-10.159) C40(-3.708,-10.537) C41(-4.172,-10.159) C42(-4.636,-10.537) C43(-5.099,-10.159) C44(-5.563,-10.537) C45(-6.026,-10.159) C46(-6.49,-10.537) C47(-6.953,-10.159) C48(-7.417,-10.537) C49(-7.88,-10.159) C50(-8.344,-10.537) C51(-8.807,-10.159) C52(-9.271,-10.537) C53(-9.735,-10.159) C54(-10.198,-10.537) C55(-10.662,-10.159) C56(-11.125,-10.537) C57(-11.589,-10.159) D32(0,-9.78) H61(-13.66,-8.001) J2(14.037,-7.417) J62(-14.22,-7.544) K2(14.414,-6.953) K3(13.66,-6.953) K61(-13.66,-6.953) K62(-14.414,-6.953) L2(14.037,-6.49) L62(-14.037,-6.49) M2(14.414,-6.026) M3(13.66,-6.026) M61(-13.66,-6.026) M62(-14.414,-6.026) N2(14.037,-5.563) N62(-14.037,-5.563) P2(14.414,-5.099) P3(13.66,-5.099) P61(-13.66,-5.099) P62(-14.414,-5.099) R2(14.037,-4.636) R62(-14.037,-4.636) T2(14.414,-4.172) T3(13.66,-4.172) T61(-13.66,-4.172) T62(-14.414,-4.172) U2(14.037,-3.708) U62(-14.037,-3.708) V2(14.414,-3.245) V3(13.66,-3.245) V61(-13.66,-3.245) V62(-14.414,-3.245) W2(14.037,-2.781) W62(-14.037,-2.781) Y2(14.414,-2.318) Y3(13.66,-2.318) Y61(-13.66,-2.318) Y62(-14.414,-2.318)
  round 0.33 smd: AA18(6.299,-1.448) AA20(5.512,-1.448) AA22(4.724,-1.448) AA23(3.937,-1.448) AA25(3.15,-1.448) AA27(2.362,-1.448) AA28(1.575,-1.448) AA30(0.787,-1.448) AA32(0,-1.448) AA34(-0.787,-1.448) AA36(-1.575,-1.448) AA37(-2.362,-1.448) AA39(-3.15,-1.448) AA41(-3.937,-1.448) AA42(-4.724,-1.448) AA44(-5.512,-1.448) AA46(-6.299,-1.448) AC18(6.299,-0.724) AC20(5.512,-0.724) AC22(4.724,-0.724) AC23(3.937,-0.724) AC25(3.15,-0.724) AC27(2.362,-0.724) AC28(1.575,-0.724) AC30(0.787,-0.724) AC32(0,-0.724) AC34(-0.787,-0.724) AC36(-1.575,-0.724) AC37(-2.362,-0.724) AC39(-3.15,-0.724) AC41(-3.937,-0.724) AC42(-4.724,-0.724) AC44(-5.512,-0.724) AC46(-6.299,-0.724) AE18(6.299,0) AE20(5.512,0) AE22(4.724,0) AE23(3.937,0) AE25(3.15,0) AE27(2.362,0) AE28(1.575,0) AE30(0.787,0) AE32(0,0) AE34(-0.787,0) AE36(-1.575,0) AE37(-2.362,0) AE39(-3.15,0) AE41(-3.937,0) AE42(-4.724,0) AE44(-5.512,0) AE46(-6.299,0) AG18(6.299,0.724) AG20(5.512,0.724) AG22(4.724,0.724) AG23(3.937,0.724) AG25(3.15,0.724) AG27(2.362,0.724) AG28(1.575,0.724) AG30(0.787,0.724) AG32(0,0.724) AG34(-0.787,0.724) AG36(-1.575,0.724) AG37(-2.362,0.724) AG39(-3.15,0.724) AG41(-3.937,0.724) AG42(-4.724,0.724) AG44(-5.512,0.724) AG46(-6.299,0.724) AJ18(6.299,1.448) AJ20(5.512,1.448) AJ22(4.724,1.448) AJ23(3.937,1.448) AJ25(3.15,1.448) AJ27(2.362,1.448) AJ28(1.575,1.448) AJ30(0.787,1.448) AJ32(0,1.448) AJ34(-0.787,1.448) AJ36(-1.575,1.448) AJ37(-2.362,1.448) AJ39(-3.15,1.448) AJ41(-3.937,1.448) AJ42(-4.724,1.448) AJ44(-5.512,1.448) AJ46(-6.299,1.448) AK18(6.299,2.172) AK20(5.512,2.172) AK22(4.724,2.172) AK23(3.937,2.172) AK25(3.15,2.172) AK27(2.362,2.172) AK28(1.575,2.172) AK30(0.787,2.172) AK32(0,2.172) AK34(-0.787,2.172) AK36(-1.575,2.172) AK37(-2.362,2.172) AK39(-3.15,2.172) AK41(-3.937,2.172) AK42(-4.724,2.172) AK44(-5.512,2.172) AK46(-6.299,2.172) AM18(6.299,2.896) AM20(5.512,2.896) AM22(4.724,2.896) AM23(3.937,2.896) AM25(3.15,2.896) AM27(2.362,2.896) AM28(1.575,2.896) AM30(0.787,2.896) AM32(0,2.896) AM34(-0.787,2.896) AM36(-1.575,2.896) AM37(-2.362,2.896) AM39(-3.15,2.896) AM41(-3.937,2.896) AM42(-4.724,2.896) AM44(-5.512,2.896) AM46(-6.299,2.896) AN18(6.299,3.619) AN20(5.512,3.619) AN22(4.724,3.619) AN23(3.937,3.619) AN25(3.15,3.619) AN27(2.362,3.619) AN28(1.575,3.619) AN30(0.787,3.619) AN32(0,3.619) AN34(-0.787,3.619) AN36(-1.575,3.619) AN37(-2.362,3.619) AN39(-3.15,3.619) AN41(-3.937,3.619) AN42(-4.724,3.619) AN44(-5.512,3.619) AN46(-6.299,3.619) U18(6.299,-3.619) U20(5.512,-3.619) U22(4.724,-3.619) U23(3.937,-3.619) U25(3.15,-3.619) U27(2.362,-3.619) U28(1.575,-3.619) U30(0.787,-3.619) U32(0,-3.619) U34(-0.787,-3.619) U36(-1.575,-3.619) U37(-2.362,-3.619) U39(-3.15,-3.619) U41(-3.937,-3.619) U42(-4.724,-3.619) U44(-5.512,-3.619) U46(-6.299,-3.619) V18(6.299,-2.896) V20(5.512,-2.896) V22(4.724,-2.896) V23(3.937,-2.896) V25(3.15,-2.896) V27(2.362,-2.896) V28(1.575,-2.896) V30(0.787,-2.896) V32(0,-2.896) V34(-0.787,-2.896) V36(-1.575,-2.896) V37(-2.362,-2.896) V39(-3.15,-2.896) V41(-3.937,-2.896) V42(-4.724,-2.896) V44(-5.512,-2.896) V46(-6.299,-2.896) Y18(6.299,-2.172) Y20(5.512,-2.172) Y22(4.724,-2.172) Y23(3.937,-2.172) Y25(3.15,-2.172) Y27(2.362,-2.172) Y28(1.575,-2.172) Y30(0.787,-2.172) Y32(0,-2.172) Y34(-0.787,-2.172) Y36(-1.575,-2.172) Y37(-2.362,-2.172) Y39(-3.15,-2.172) Y41(-3.937,-2.172) Y42(-4.724,-2.172) Y44(-5.512,-2.172) Y46(-6.299,-2.172)
  round 0.305 smd: AB5(12.999,-1.397) AB6(12.288,-1.397) AB7(11.577,-1.397) AB9(10.866,-1.397) AB10(10.154,-1.397) AB12(9.443,-1.397) AB13(8.732,-1.397) AB15(8.021,-1.397) AB16(7.309,-1.397) AB48(-7.309,-1.397) AB49(-8.021,-1.397) AB51(-8.732,-1.397) AB52(-9.443,-1.397) AB54(-10.154,-1.397) AB55(-10.866,-1.397) AB57(-11.577,-1.397) AB58(-12.288,-1.397) AB59(-12.999,-1.397) AC5(12.999,-0.521) AC6(12.288,-0.521) AC7(11.577,-0.521) AC9(10.866,-0.521) AC10(10.154,-0.521) AC12(9.443,-0.521) AC13(8.732,-0.521) AC15(8.021,-0.521) AC16(7.309,-0.521) AC48(-7.309,-0.521) AC49(-8.021,-0.521) AC51(-8.732,-0.521) AC52(-9.443,-0.521) AC54(-10.154,-0.521) AC55(-10.866,-0.521) AC57(-11.577,-0.521) AC58(-12.288,-0.521) AC59(-12.999,-0.521) AE5(12.644,0) AE7(11.932,0) AE8(11.221,0) AE10(10.51,0) AE11(9.799,0) AE13(9.088,0) AE14(8.376,0) AE16(7.665,0) AE17(6.954,0) AE47(-6.954,0) AE48(-7.665,0) AE50(-8.376,0) AE51(-9.088,0) AE53(-9.799,0) AE54(-10.51,0) AE56(-11.221,0) AE57(-11.932,0) AE59(-12.644,0) AG5(12.999,0.521) AG6(12.288,0.521) AG7(11.577,0.521) AG9(10.866,0.521) AG10(10.154,0.521) AG12(9.443,0.521) AG13(8.732,0.521) AG15(8.021,0.521) AG16(7.309,0.521) AG48(-7.309,0.521) AG49(-8.021,0.521) AG51(-8.732,0.521) AG52(-9.443,0.521) AG54(-10.154,0.521) AG55(-10.866,0.521) AG57(-11.577,0.521) AG58(-12.288,0.521) AG59(-12.999,0.521) AH5(12.999,1.397) AH6(12.288,1.397) AH7(11.577,1.397) AH9(10.866,1.397) AH10(10.154,1.397) AH12(9.443,1.397) AH13(8.732,1.397) AH15(8.021,1.397) AH16(7.309,1.397) AH48(-7.309,1.397) AH49(-8.021,1.397) AH51(-8.732,1.397) AH52(-9.443,1.397) AH54(-10.154,1.397) AH55(-10.866,1.397) AH57(-11.577,1.397) AH58(-12.288,1.397) AH59(-12.999,1.397) AK5(12.999,2.349) AK6(12.288,2.349) AK7(11.577,2.349) AK9(10.866,2.349) AK10(10.154,2.349) AK12(9.443,2.349) AK13(8.732,2.349) AK15(8.021,2.349) AK16(7.309,2.349) AK48(-7.309,2.349) AK49(-8.021,2.349) AK51(-8.732,2.349) AK52(-9.443,2.35) AK54(-10.154,2.349) AK55(-10.866,2.349) AK57(-11.577,2.349) AK58(-12.288,2.349) AK59(-12.999,2.349) AM5(12.999,3.226) AM6(12.288,3.226) AM7(11.577,3.226) AM9(10.866,3.226) AM10(10.154,3.226) AM12(9.443,3.226) AM13(8.732,3.226) AM15(8.021,3.226) AM16(7.309,3.226) AM48(-7.309,3.226) AM49(-8.021,3.226) AM51(-8.732,3.226) AM52(-9.443,3.226) AM54(-10.154,3.226) AM55(-10.866,3.226) AM57(-11.577,3.226) AM58(-12.288,3.226) AM59(-12.999,3.226) AN5(12.644,3.746) AN7(11.932,3.747) AN8(11.221,3.747) AN10(10.51,3.747) AN11(9.799,3.747) AN13(9.088,3.747) AN14(8.376,3.747) AN16(7.665,3.747) AN17(6.954,3.747) AN47(-6.954,3.747) AN48(-7.665,3.747) AN50(-8.376,3.747) AN51(-9.088,3.747) AN53(-9.799,3.746) AN54(-10.51,3.747) AN56(-11.221,3.747) AN57(-11.932,3.747) AN59(-12.644,3.747) AP5(12.999,4.267) AP6(12.288,4.267) AP7(11.577,4.267) AP9(10.866,4.267) AP10(10.154,4.267) AP12(9.443,4.267) AP13(8.732,4.267) AP15(8.021,4.267) AP49(-8.021,4.267) AP51(-8.732,4.267) AP52(-9.443,4.267) AP54(-10.154,4.267) AP55(-10.866,4.267) AP57(-11.577,4.267) AP58(-12.288,4.267) AP59(-12.999,4.267) AR17(7.004,4.432) AR19(6.096,4.432) AR21(5.144,4.432) AR23(4.223,4.432) AR25(3.27,4.432) AR27(2.349,4.432) AR29(1.397,4.432) AR30(0.476,4.432) AR32(0,4.787) AR34(-0.476,4.432) AR35(-1.397,4.432) AR37(-2.349,4.432) AR39(-3.27,4.432) AR41(-4.223,4.432) AR43(-5.144,4.432) AR45(-6.096,4.432) AR47(-7.004,4.432) AT5(12.999,5.144) AT6(12.288,5.144) AT7(11.577,5.144) AT9(10.866,5.144) AT10(10.154,5.144) AT12(9.443,5.144) AT13(8.732,5.144) AT16(7.626,5.143) AT17(7.004,5.143) AT19(6.096,5.143) AT21(5.144,5.143) AT23(4.223,5.143) AT25(3.27,5.143) AT27(2.349,5.143) AT29(1.397,5.143) AT30(0.476,5.143) AT34(-0.476,5.143) AT35(-1.397,5.143) AT37(-2.349,5.143) AT39(-3.27,5.143) AT41(-4.223,5.143) AT43(-5.144,5.143) AT45(-6.096,5.143) AT47(-7.004,5.143) AT48(-7.626,5.143) AT51(-8.732,5.144) AT52(-9.443,5.144) AT54(-10.154,5.144) AT55(-10.866,5.144) AT57(-11.577,5.144) AT58(-12.288,5.144) AT59(-12.999,5.144) AU32(0,5.499) AV5(12.999,6.096) AV6(12.288,6.096) AV7(11.577,6.096) AV9(10.866,6.096) AV10(10.154,6.096) AV12(9.443,6.096) AV14(8.534,5.854) AV16(7.626,5.854) AV17(7.004,5.854) AV19(6.096,5.854) AV21(5.144,5.854) AV23(4.223,5.854) AV25(3.27,5.854) AV27(2.349,5.854) AV29(1.397,5.854) AV30(0.476,5.854) AV32(0,6.21) AV34(-0.476,5.854) AV35(-1.397,5.854) AV37(-2.349,5.854) AV39(-3.27,5.854) AV41(-4.223,5.854) AV43(-5.144,5.854) AV45(-6.096,5.854) AV47(-7.004,5.854) AV48(-7.626,5.854) AV50(-8.534,5.854) AV52(-9.443,6.096) AV54(-10.154,6.096) AV55(-10.866,6.096) AV57(-11.577,6.096) AV58(-12.288,6.096) AV59(-12.999,6.096) AW14(8.534,6.565) AW16(7.626,6.565) AW17(7.004,6.565) AW19(6.096,6.565) AW21(5.144,6.565) AW23(4.223,6.565) AW25(3.27,6.565) AW27(2.349,6.565) AW29(1.397,6.565) AW30(0.476,6.565) AW34(-0.476,6.565) AW35(-1.397,6.565) AW37(-2.349,6.565) AW39(-3.27,6.565) AW41(-4.223,6.565) AW43(-5.144,6.565) AW45(-6.096,6.565) AW47(-7.004,6.565) AW48(-7.626,6.565) AW50(-8.534,6.565) AY5(12.999,7.048) AY6(12.288,7.048) AY7(11.577,7.049) AY9(10.866,7.048) AY10(10.154,7.048) AY32(0,6.921) AY54(-10.154,7.048) AY55(-10.866,7.049) AY57(-11.577,7.048) AY58(-12.288,7.048) AY59(-12.999,7.048) B7(11.968,-10.72) BA12(9.487,7.277) BA14(8.534,7.277) BA16(7.626,7.277) BA17(7.004,7.277) BA19(6.096,7.277) BA21(5.144,7.277) BA23(4.223,7.277) BA25(3.27,7.277) BA27(2.349,7.277) BA29(1.397,7.277) BA30(0.476,7.277) BA32(0,7.632) BA34(-0.476,7.277) BA35(-1.397,7.277) BA37(-2.349,7.277) BA39(-3.27,7.277) BA41(-4.223,7.277) BA43(-5.144,7.277) BA45(-6.096,7.277) BA47(-7.004,7.277) BA48(-7.626,7.277) BA50(-8.534,7.277) BA52(-9.487,7.277) BB3(13.66,8.001) BB5(12.999,8.001) BB6(12.288,8.001) BB7(11.577,8.001) BB10(10.439,7.988) BB12(9.487,7.988) BB14(8.534,7.988) BB16(7.626,7.988) BB17(7.004,7.988) BB19(6.096,7.988) BB21(5.144,7.988) BB23(4.223,7.988) BB25(3.27,7.988) BB27(2.349,7.988) BB29(1.397,7.988) BB30(0.476,7.988) BB34(-0.476,7.988) BB35(-1.397,7.988) BB37(-2.349,7.988) BB39(-3.27,7.988) BB41(-4.223,7.988) BB43(-5.144,7.988) BB45(-6.096,7.988) BB47(-7.004,7.988) BB48(-7.626,7.988) BB50(-8.534,7.988) BB52(-9.487,7.988) BB54(-10.439,7.988) BB57(-11.577,8.001) BB58(-12.288,8.001) BB59(-12.999,8.001) BB61(-13.66,8.001) BC32(0,8.343) BD3(13.629,8.89) BD5(12.961,8.89) BD6(12.288,8.89) BD8(11.392,8.699) BD10(10.439,8.699) BD12(9.487,8.699) BD14(8.534,8.699) BD16(7.626,8.699) BD17(7.004,8.699) BD19(6.096,8.699) BD21(5.144,8.699) BD23(4.223,8.699) BD25(3.27,8.699) BD27(2.349,8.699) BD29(1.397,8.699) BD30(0.476,8.699) BD32(0,9.055) BD34(-0.476,8.699) BD35(-1.397,8.699) BD37(-2.349,8.699) BD39(-3.27,8.699) BD41(-4.223,8.699) BD43(-5.144,8.699) BD45(-6.096,8.699) BD47(-7.004,8.699) BD48(-7.626,8.699) BD50(-8.534,8.699) BD52(-9.487,8.699) BD54(-10.439,8.699) BD56(-11.392,8.699) BD58(-12.288,8.89) BD59(-12.961,8.89) BD61(-13.629,8.89) BE8(11.392,9.41) BE10(10.439,9.41) BE12(9.487,9.41) BE14(8.534,9.41) BE16(7.626,9.41) BE17(7.004,9.41) BE19(6.096,9.41) BE21(5.144,9.41) BE23(4.223,9.41) BE25(3.27,9.41) BE27(2.349,9.41) BE29(1.397,9.41) BE30(0.476,9.41) BE34(-0.476,9.41) BE35(-1.397,9.41) BE37(-2.349,9.41) BE39(-3.27,9.41) BE41(-4.223,9.41) BE43(-5.144,9.41) BE45(-6.096,9.41) BE47(-7.004,9.41) BE48(-7.626,9.41) BE50(-8.534,9.41) BE52(-9.487,9.41) BE54(-10.439,9.41) BE56(-11.392,9.41) BF3(13.629,9.682) BF5(12.961,9.682) BF6(12.344,10.121) BF58(-12.344,10.121) BF59(-12.961,9.682) BF61(-13.629,9.682) D4(13.139,-10.121) D6(12.255,-10.121) D8(11.392,-10.121) D58(-12.344,-10.121) D59(-12.961,-9.682) D61(-13.629,-9.682) E3(13.622,-9.624) E4(13.025,-9.474) E6(12.255,-9.41) E8(11.392,-9.41) E10(10.439,-9.41) E12(9.487,-9.41) E14(8.534,-9.41) E16(7.626,-9.41) E17(7.004,-9.41) E19(6.096,-9.41) E21(5.144,-9.41) E23(4.223,-9.41) E25(3.27,-9.41) E27(2.349,-9.41) E29(1.397,-9.41) E30(0.476,-9.41) E34(-0.476,-9.41) E35(-1.397,-9.41) E37(-2.349,-9.41) E39(-3.27,-9.41) E41(-4.223,-9.41) E43(-5.144,-9.41) E45(-6.096,-9.41) E47(-7.004,-9.41) E48(-7.626,-9.41) E50(-8.534,-9.41) E52(-9.487,-9.41) E54(-10.439,-9.41) E56(-11.392,-9.41) F3(13.698,-8.7) F5(12.999,-8.7) F6(12.288,-8.7) F8(11.392,-8.699) F10(10.439,-8.699) F12(9.487,-8.699) F14(8.534,-8.699) F16(7.626,-8.699) F17(7.004,-8.699) F19(6.096,-8.699) F21(5.144,-8.699) F23(4.223,-8.699) F25(3.27,-8.699) F27(2.349,-8.699) F29(1.397,-8.699) F30(0.476,-8.699) F32(0,-9.055) F34(-0.476,-8.699) F35(-1.397,-8.699) F37(-2.349,-8.699) F39(-3.27,-8.699) F41(-4.223,-8.699) F43(-5.144,-8.699) F45(-6.096,-8.699) F47(-7.004,-8.699) F48(-7.626,-8.699) F50(-8.534,-8.699) F52(-9.487,-8.699) F54(-10.439,-8.699) F56(-11.392,-8.699) F58(-12.288,-8.89) F59(-12.961,-8.89) F61(-13.629,-8.89) G32(0,-8.343) H3(13.859,-8.02) H5(12.999,-7.912) H6(12.288,-7.912) H7(11.577,-7.912) H10(10.439,-7.988) H12(9.487,-7.988) H14(8.534,-7.988) H16(7.626,-7.988) H17(7.004,-7.988) H19(6.096,-7.988) H21(5.144,-7.988) H23(4.223,-7.988) H25(3.27,-7.988) H27(2.349,-7.988) H29(1.397,-7.988) H30(0.476,-7.988) H34(-0.476,-7.988) H35(-1.397,-7.988) H37(-2.349,-7.988) H39(-3.27,-7.988) H41(-4.223,-7.988) H43(-5.144,-7.988) H45(-6.096,-7.988) H47(-7.004,-7.988) H48(-7.626,-7.988) H50(-8.534,-7.988) H52(-9.487,-7.988) H54(-10.439,-7.988) H57(-11.577,-8.001) H58(-12.288,-8.001) H59(-12.999,-8.001) J12(9.487,-7.277) J14(8.534,-7.277) J16(7.626,-7.277) J17(7.004,-7.277) J19(6.096,-7.277) J21(5.144,-7.277) J23(4.223,-7.277) J25(3.27,-7.277) J27(2.349,-7.277) J29(1.397,-7.277) J30(0.476,-7.277) J32(0,-7.632) J34(-0.476,-7.277) J35(-1.397,-7.277) J37(-2.349,-7.277) J39(-3.27,-7.277) J41(-4.223,-7.277) J43(-5.144,-7.277) J45(-6.096,-7.277) J47(-7.004,-7.277) J48(-7.626,-7.277) J50(-8.534,-7.277) J52(-9.487,-7.277) K5(12.999,-7.048) K6(12.288,-7.048) K7(11.577,-7.048) K9(10.866,-7.049) K10(10.154,-7.048) K32(0,-6.921) K54(-10.154,-7.048) K55(-10.866,-7.048) K57(-11.577,-7.049) K58(-12.288,-7.048) K59(-12.999,-7.048) L14(8.534,-6.565) L16(7.626,-6.565) L17(7.004,-6.565) L19(6.096,-6.565) L21(5.144,-6.565) L23(4.223,-6.565) L25(3.27,-6.565) L27(2.349,-6.565) L29(1.397,-6.565) L30(0.476,-6.565) L34(-0.476,-6.565) L35(-1.397,-6.565) L37(-2.349,-6.565) L39(-3.27,-6.565) L41(-4.223,-6.565) L43(-5.144,-6.565) L45(-6.096,-6.565) L47(-7.004,-6.565) L48(-7.626,-6.565) L50(-8.534,-6.565) M5(12.999,-6.096) M6(12.288,-6.096) M7(11.577,-6.096) M9(10.866,-6.096) M10(10.154,-6.096) M12(9.443,-6.096) M14(8.534,-5.854) M16(7.626,-5.854) M17(7.004,-5.854) M19(6.096,-5.854) M21(5.144,-5.854) M23(4.223,-5.854) M25(3.27,-5.854) M27(2.349,-5.854) M29(1.397,-5.854) M30(0.476,-5.854) M32(0,-6.21) M34(-0.476,-5.854) M35(-1.397,-5.854) M37(-2.349,-5.854) M39(-3.27,-5.854) M41(-4.223,-5.854) M43(-5.144,-5.854) M45(-6.096,-5.854) M47(-7.004,-5.854) M48(-7.626,-5.854) M50(-8.534,-5.854) M52(-9.443,-6.096) M54(-10.154,-6.096) M55(-10.866,-6.096) M57(-11.577,-6.096) M58(-12.288,-6.096) M59(-12.999,-6.096) N32(0,-5.499) P5(12.999,-5.144) P6(12.288,-5.144) P7(11.577,-5.144) P9(10.866,-5.144) P10(10.154,-5.144) P12(9.443,-5.144) P13(8.732,-5.144) P16(7.626,-5.143) P17(7.004,-5.143) P19(6.096,-5.143) P21(5.144,-5.143) P23(4.223,-5.143) P25(3.27,-5.143) P27(2.349,-5.143) P29(1.397,-5.143) P30(0.476,-5.143) P34(-0.476,-5.143) P35(-1.397,-5.143) P37(-2.349,-5.143) P39(-3.27,-5.143) P41(-4.223,-5.143) P43(-5.144,-5.143) P45(-6.096,-5.143) P47(-7.004,-5.143) P48(-7.626,-5.143) P51(-8.732,-5.144) P52(-9.443,-5.144) P54(-10.154,-5.144) P55(-10.866,-5.144) P57(-11.577,-5.144) P58(-12.288,-5.144) P59(-12.999,-5.144) R17(7.004,-4.432) R19(6.096,-4.432) R21(5.144,-4.432) R23(4.223,-4.432) R25(3.27,-4.432) R27(2.349,-4.432) R29(1.397,-4.432) R30(0.476,-4.432) R32(0,-4.787) R34(-0.476,-4.432) R35(-1.397,-4.432) R37(-2.349,-4.432) R39(-3.27,-4.432) R41(-4.223,-4.432) R43(-5.144,-4.432) R45(-6.096,-4.432) R47(-7.004,-4.432) T5(12.999,-4.267) T6(12.288,-4.267) T7(11.577,-4.267) T9(10.866,-4.267) T10(10.154,-4.267) T12(9.443,-4.267) T13(8.732,-4.267) T15(8.021,-4.267) T49(-8.021,-4.267) T51(-8.732,-4.267) T52(-9.443,-4.267) T54(-10.154,-4.267) T55(-10.866,-4.267) T57(-11.577,-4.267) T58(-12.288,-4.267) T59(-12.999,-4.267) U5(12.644,-3.747) U7(11.932,-3.747) U8(11.221,-3.747) U10(10.51,-3.747) U11(9.799,-3.746) U13(9.088,-3.747) U14(8.376,-3.747) U16(7.665,-3.747) U17(6.954,-3.747) U47(-6.954,-3.747) U48(-7.665,-3.747) U50(-8.376,-3.747) U51(-9.088,-3.747) U53(-9.799,-3.747) U54(-10.51,-3.747) U56(-11.221,-3.747) U57(-11.932,-3.747) U59(-12.644,-3.746) V5(12.999,-3.226) V6(12.288,-3.226) V7(11.577,-3.226) V9(10.866,-3.226) V10(10.154,-3.226) V12(9.443,-3.226) V13(8.732,-3.226) V15(8.021,-3.226) V16(7.309,-3.226) V48(-7.309,-3.226) V49(-8.021,-3.226) V51(-8.732,-3.226) V52(-9.443,-3.226) V54(-10.154,-3.226) V55(-10.866,-3.226) V57(-11.577,-3.226) V58(-12.288,-3.226) V59(-12.999,-3.226) Y5(12.999,-2.349) Y6(12.288,-2.349) Y7(11.577,-2.349) Y9(10.866,-2.349) Y10(10.154,-2.349) Y12(9.443,-2.35) Y13(8.732,-2.349) Y15(8.021,-2.349) Y16(7.309,-2.349) Y48(-7.309,-2.349) Y49(-8.021,-2.349) Y51(-8.732,-2.349) Y52(-9.443,-2.349) Y54(-10.154,-2.349) Y55(-10.866,-2.349) Y57(-11.577,-2.349) Y58(-12.288,-2.349) Y59(-12.999,-2.349)
